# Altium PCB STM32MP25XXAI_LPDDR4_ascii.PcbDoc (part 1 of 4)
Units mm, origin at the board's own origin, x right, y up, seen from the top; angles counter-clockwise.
Board outline 172 x 137 mm, 4 copper layers (Top Layer, Signal Layer 1, Signal Layer 2, Bottom Layer), stack 1.614 mm thick; 188 components, 144 nets, 1216 pads, 838 vias.
Unrouted connection lines stored in the file: 13.
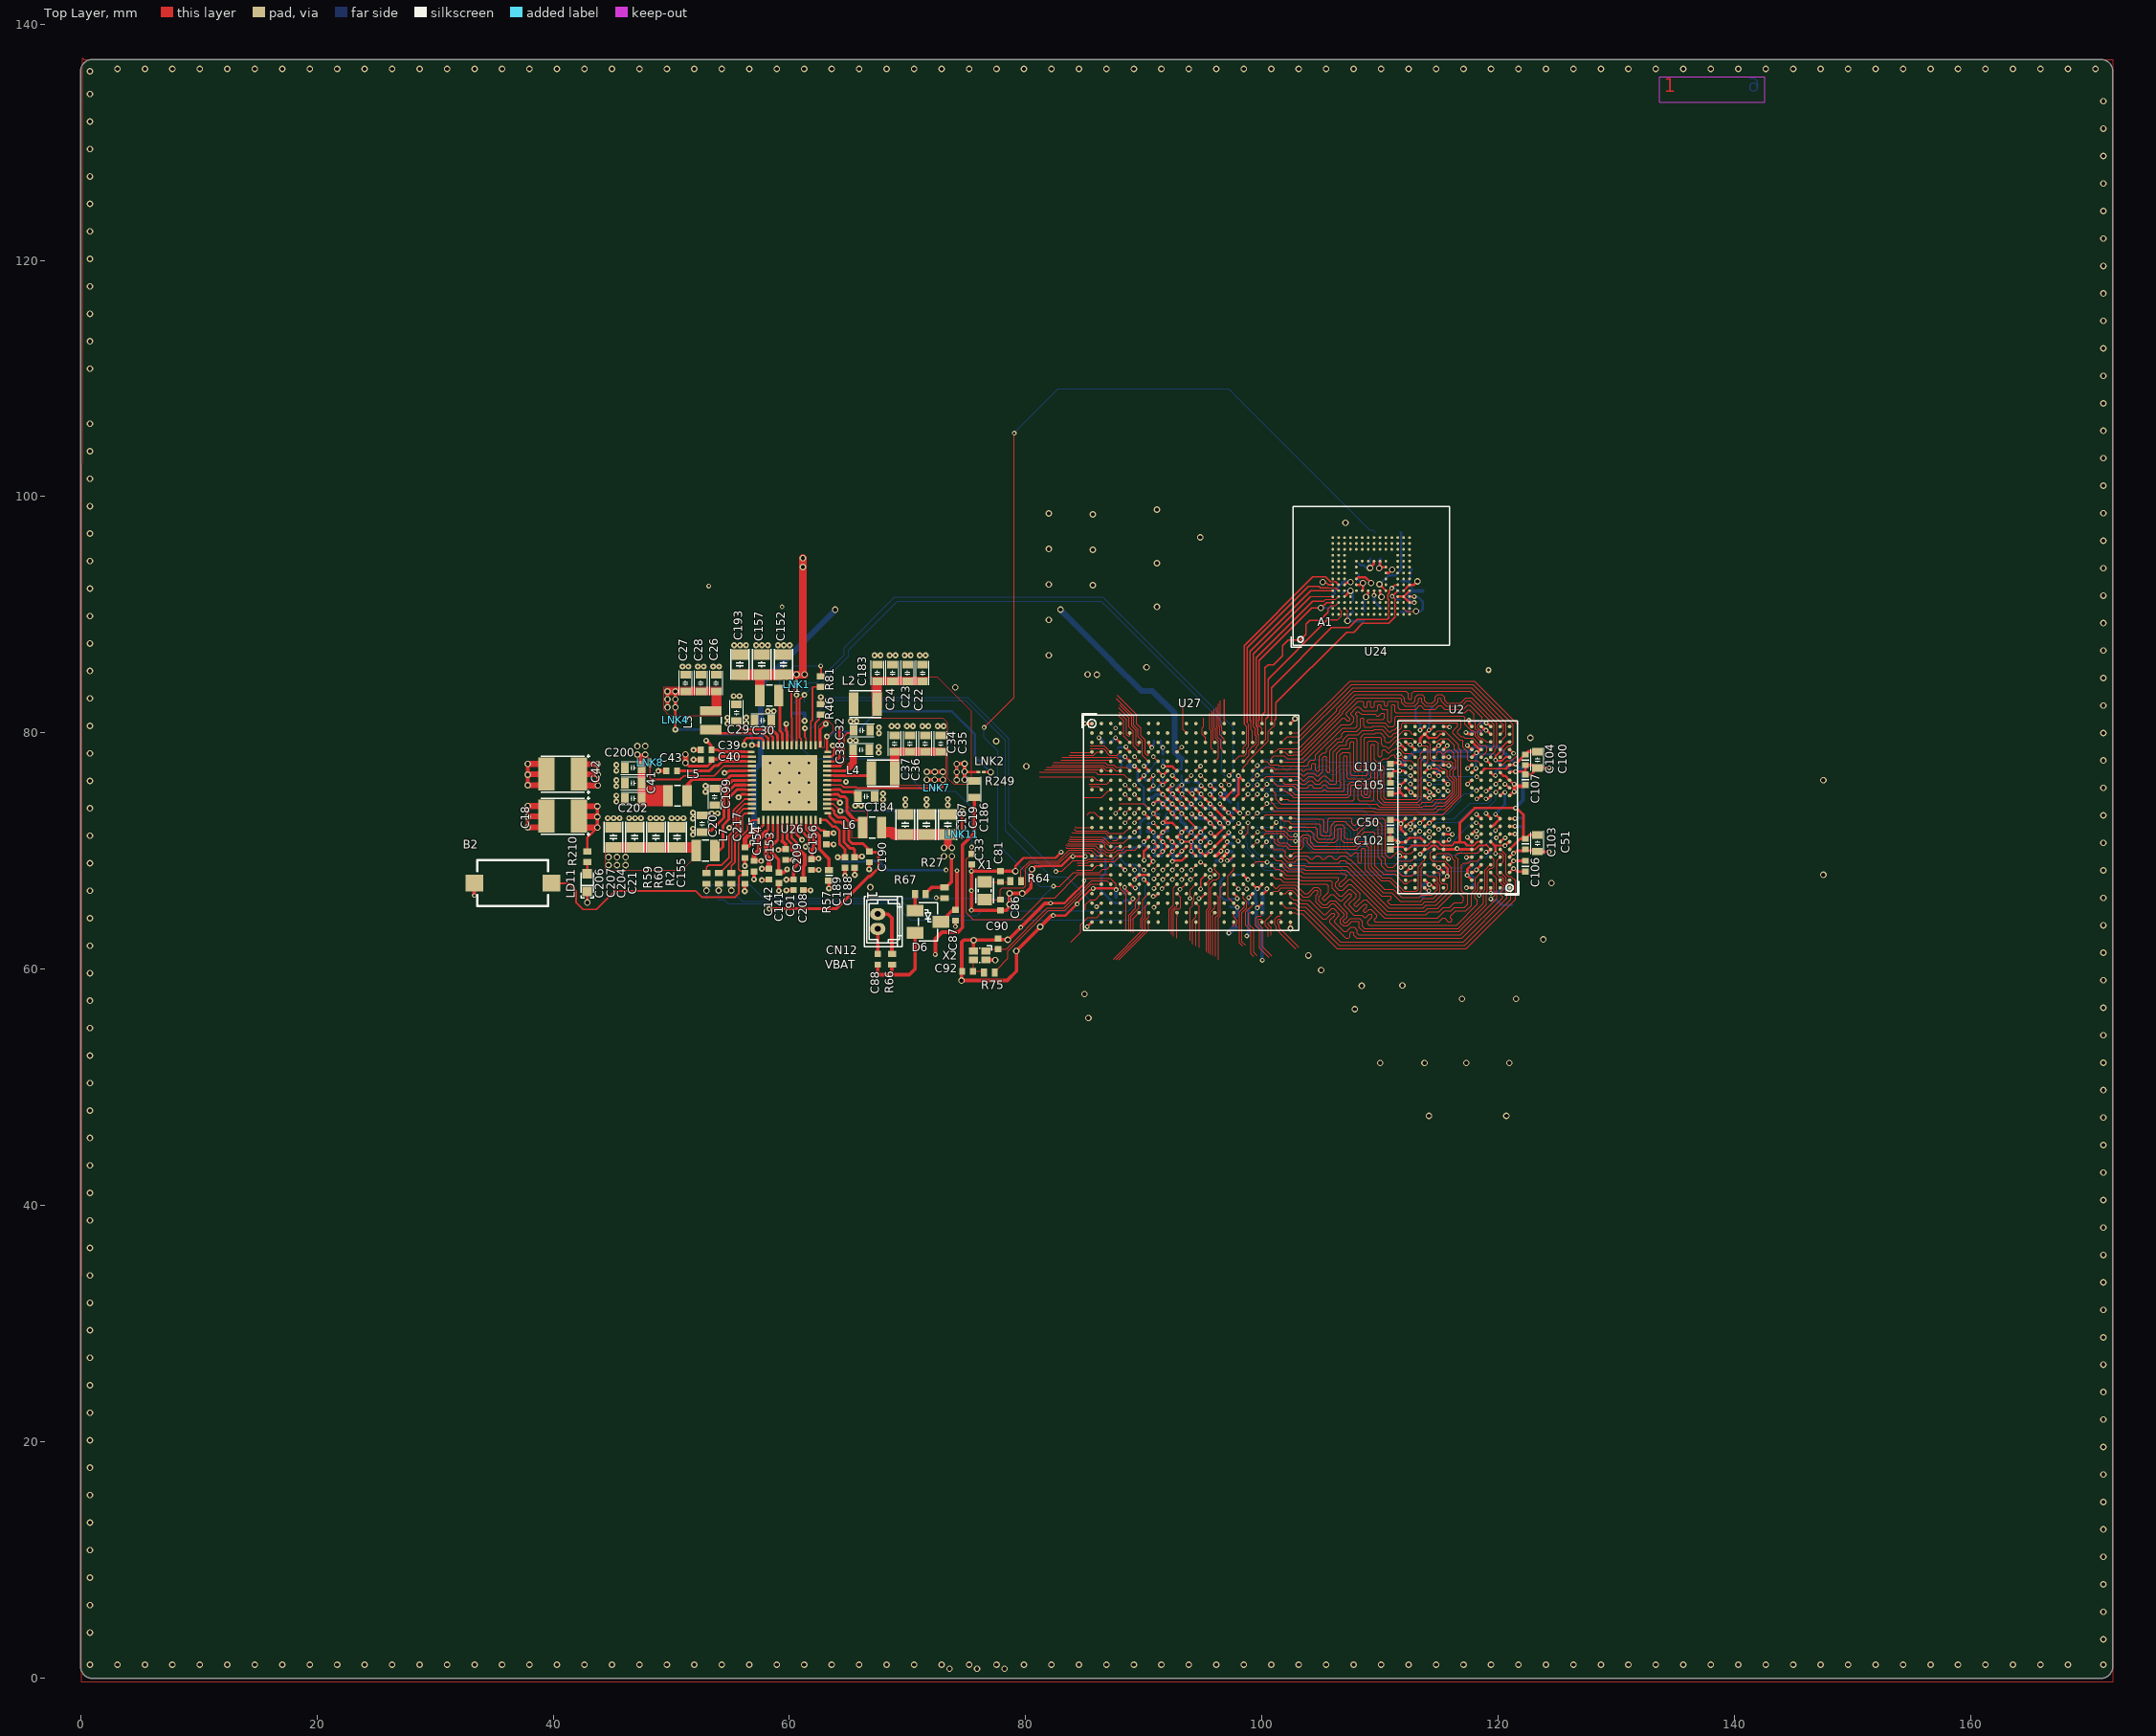
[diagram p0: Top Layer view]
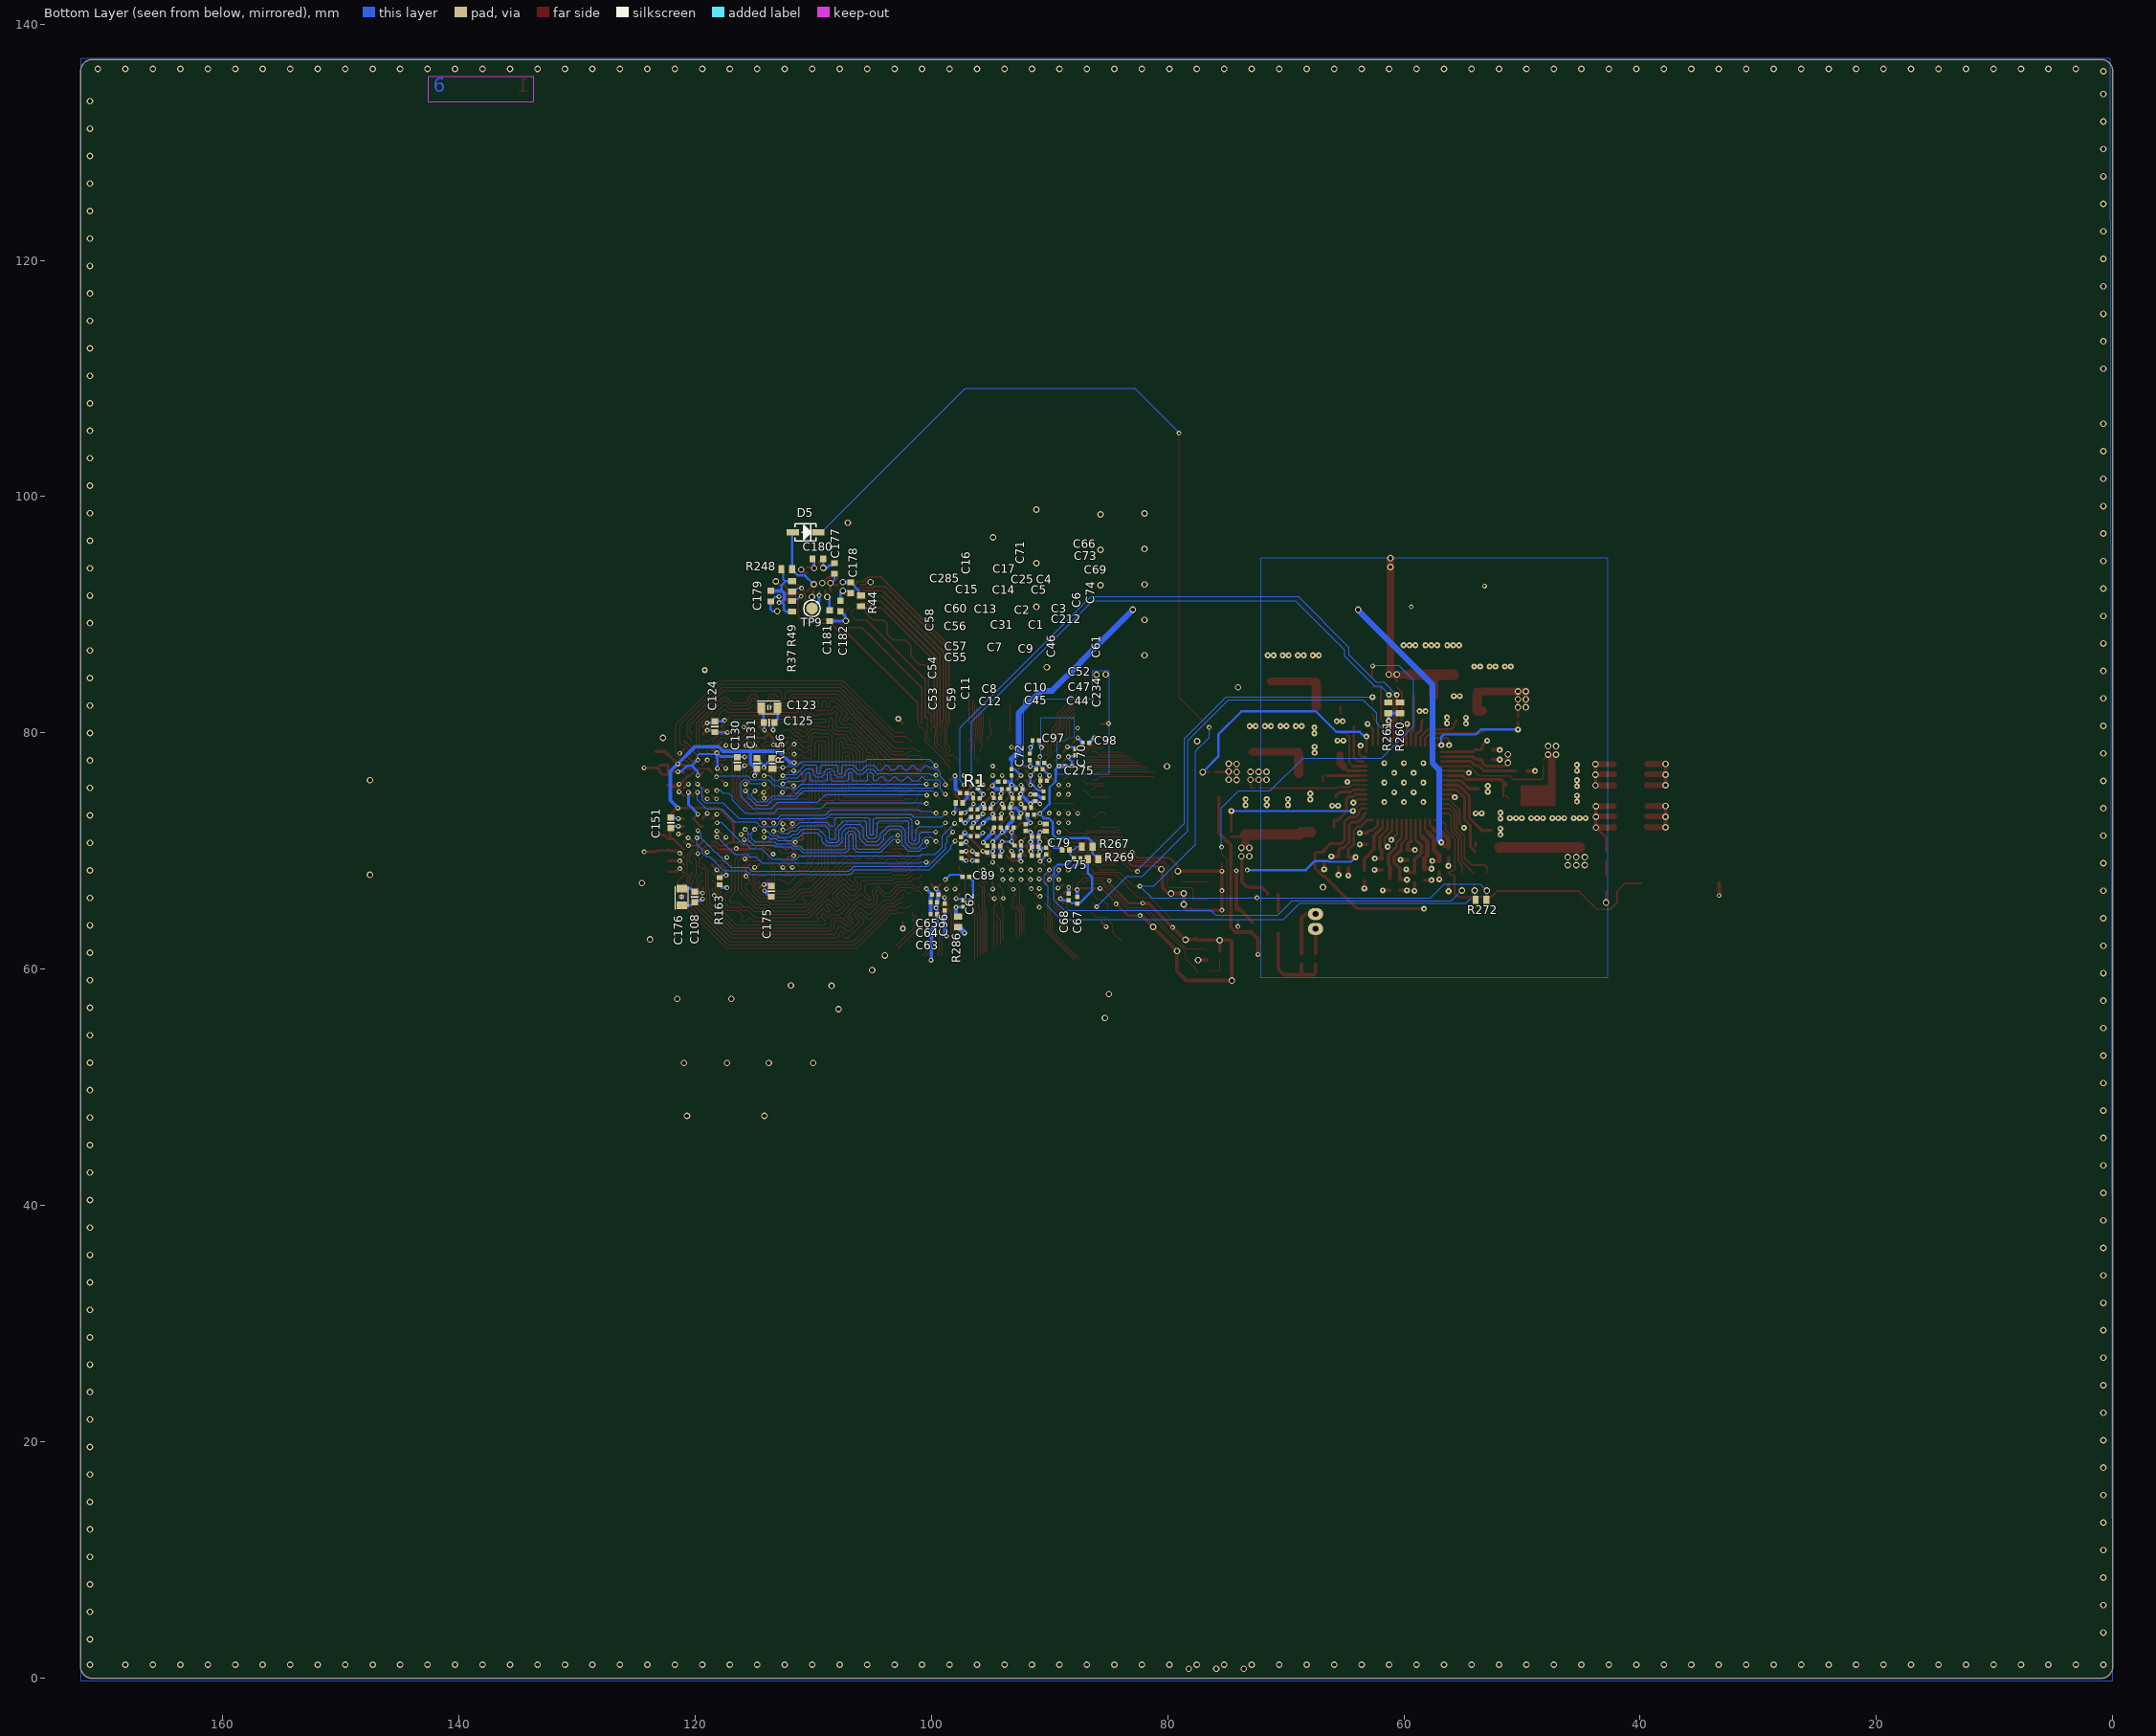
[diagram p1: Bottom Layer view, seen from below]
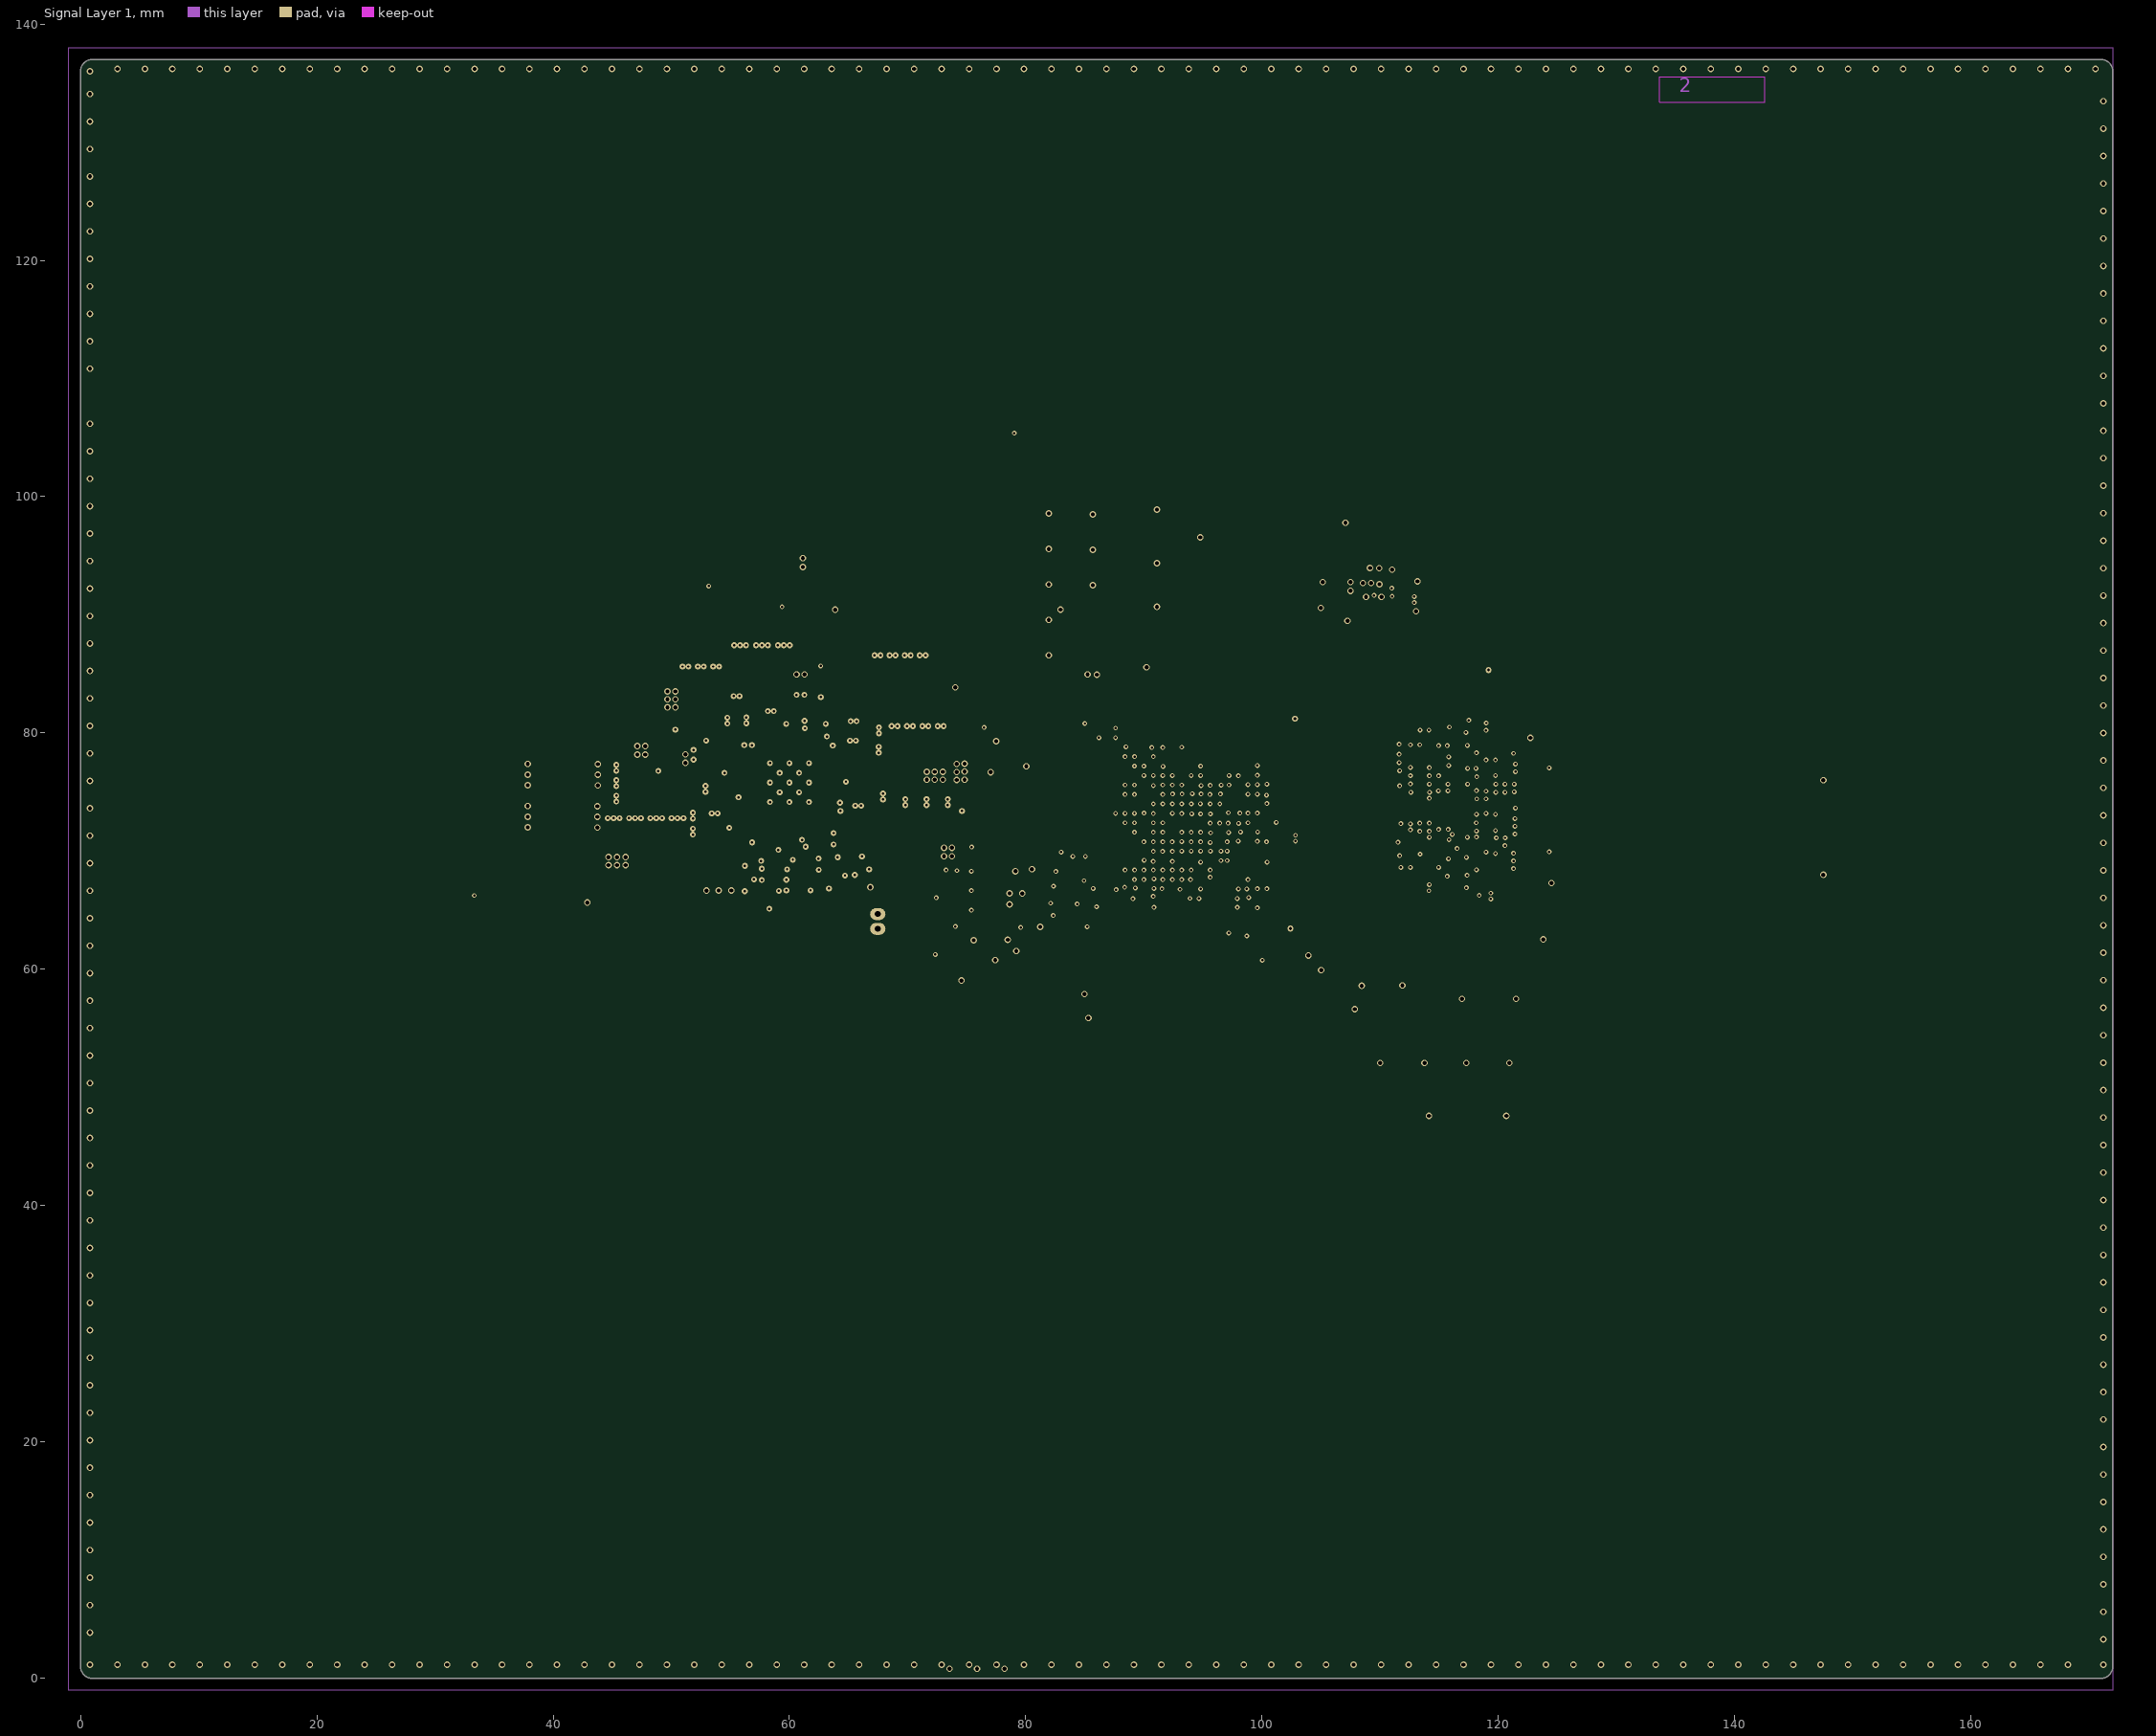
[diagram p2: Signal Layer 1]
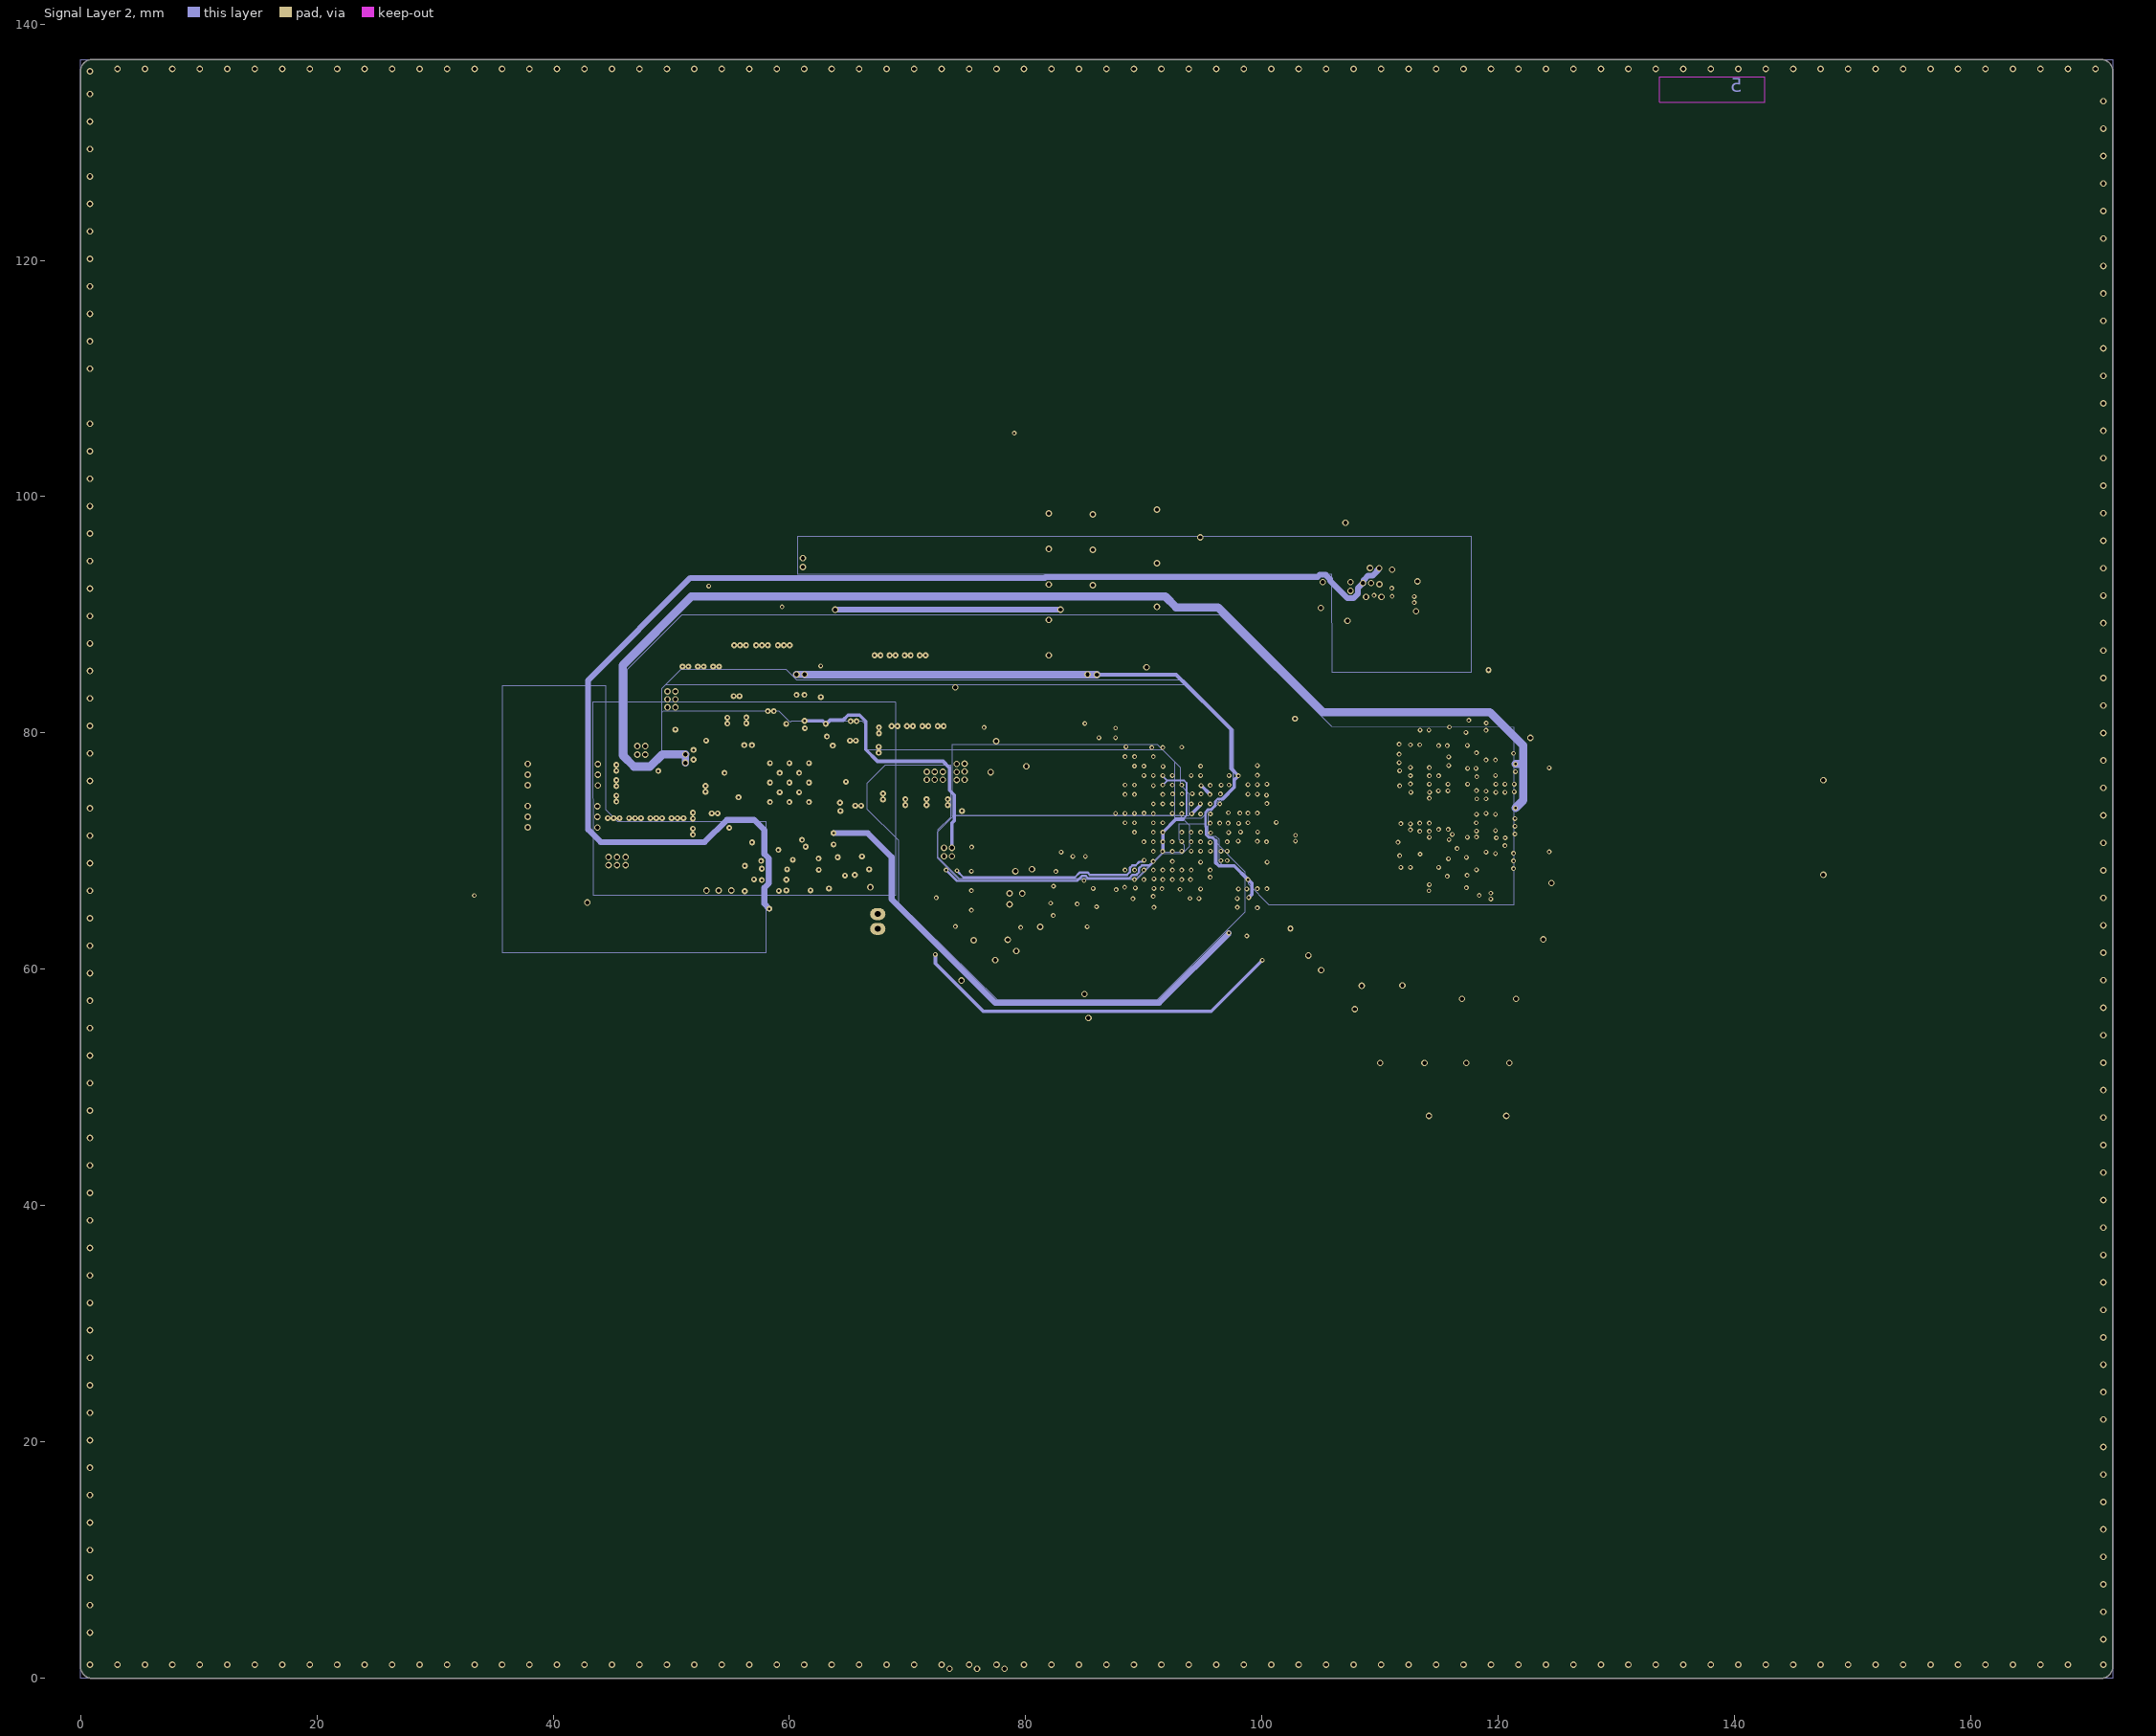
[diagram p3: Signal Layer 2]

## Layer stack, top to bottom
Top Solder: solder mask 0.025, Solder Resist, Dk 3.5
Top Layer: signal copper 0.037
Dielectric 1: prepreg 0.07, Dk 3.8
Signal Layer 1: signal copper 0.035
Dielectric 2: core 1.33, Dk 4.3
Signal Layer 2: signal copper 0.035
Dielectric 3: prepreg 0.07, Dk 3.8
Bottom Layer: signal copper 0.037
Bottom Solder: solder mask 0.025, Solder Resist, Dk 3.5

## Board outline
0,1 0,95 0,136 cw(c1,136) 1,137 171,137 cw(c171,136) 172,136 172,1 cw(c171,1) 171,0 1,0 cw(c1,1)

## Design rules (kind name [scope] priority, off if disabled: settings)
AssemblyTestPointUsage [All] p0: scope1count=1 scope1_0_kind=Board scope1_0_value=Board scope2count=1 scope2_0_kind=Board scope2_0_value=Board commentlength=0
AssemblyTestpoint [All] p0: scope1count=1 scope1_0_kind=Board scope1_0_value=Board scope2count=1 scope2_0_kind=Board scope2_0_value=Board commentlength=0
BoardOutlineClearance Silkscreen [All] p0 off: scope1count=1 scope1_0_kind=Board scope1_0_value=Board scope2count=1 scope2_0_kind=Board scope2_0_value=Board commentlength=90 gap=0 // Protel DXP Scope 1 Expression Was: OnLayer('Top Overlay') or OnLayer('Bottom Overlay')
BoardOutlineClearance [All] p0: scope1count=1 scope1_0_kind=Board scope1_0_value=Board scope2count=1 scope2_0_kind=Board scope2_0_value=Board commentlength=0 gap=0.5
BoardOutlineClearance Silkscreen [OnLayer('Top Overlay') or OnLayer('Bottom Overlay')] p1: gap=0 ignorepadtopadclearanceinfootprint=FALSE
BoardOutlineClearance [All] p2: gap=0.5 ignorepadtopadclearanceinfootprint=FALSE
Clearance Clearance_Default [All] p0: scope1count=1 scope1_0_kind=Board scope1_0_value=Board scope2count=1 scope2_0_kind=Board scope2_0_value=Board commentlength=0 gap=0.1
Clearance Clearance_Default [All] p1: gap=0.1 ignorepadtopadclearanceinfootprint=TRUE except(0: Arc-Hole Track-Hole SMDPad-Hole THPad-Hole Via-Hole Fill-Hole Poly-Hole Region-Hole Text-Hole; 0.09: Track-Track Track-SMDPad)
ComponentClearance [All] p0 off: scope1count=1 scope1_0_kind=Board scope1_0_value=Board scope2count=1 scope2_0_kind=Board scope2_0_value=Board commentlength=0 gap=0.2 collisioncheckmode=3
ComponentClearance [All] p1 off: gap=0.2 collisioncheckmode=3 verticalgap=0 showdistances=FALSE
DiffPairsRouting DiffPairsRouting_DDR_100R [All] p0 off: scope1count=1 scope1_0_kind=Board scope1_0_value=Board scope2count=1 scope2_0_kind=Board scope2_0_value=Board commentlength=78 // Protel DXP Scope 1 Expression Was: InDifferentialPairClass('DPC_DDR_100R')
DiffPairsRouting DiffPairsRouting_DDR_100R [InDifferentialPairClass('DPC_DDR_100R')] p1: maxlimit=0.16 minlimit=0.14 mostfreqgap=0.254 toplayer_mingap=0.16 toplayer_prefgap=0.16 toplayer_minwidth=0.09 toplayer_maxwidth=0.09 toplayer_prefwidth=0.09 bottomlayer_mingap=0.16 bottomlayer_prefgap=0.16 bottomlayer_minwidth=0.09 bottomlayer_maxwidth=0.09 bottomlayer_prefwidth=0.09 impedanceprofiledriven=TRUE impedanceprofileid={5106416E-43F8-41F8-8BCA-F68B3FB1C141} impedanceprofilevalue=100.000000 maxuncoupledlength=12.7
FabricationTestPointUsage [All] p0: scope1count=1 scope1_0_kind=Board scope1_0_value=Board scope2count=1 scope2_0_kind=Board scope2_0_value=Board commentlength=0 valid=0 allowmultiple=FALSE
FabricationTestpoint [All] p0: scope1count=1 scope1_0_kind=Board scope1_0_value=Board scope2count=1 scope2_0_kind=Board scope2_0_value=Board commentlength=0 side=3 testpointundercomponent=TRUE minsize=1.016 maxsize=2.54 preferedsize=1.524 minholesize=0 maxholesize=1.016 preferedholesize=0.813 testpointgrid=0.025
FanoutControl Fanout_Default [All] p0: scope1count=1 scope1_0_kind=Board scope1_0_value=Board scope2count=1 scope2_0_kind=Board scope2_0_value=Board commentlength=30 // Fanout_Default (Default Rule)
FanoutControl Fanout_Small [All] p0 off: scope1count=1 scope1_0_kind=Board scope1_0_value=Board scope2count=1 scope2_0_kind=Board scope2_0_value=Board commentlength=84 // Protel DXP Scope 1 Expression Was: (CompPinCount < 5)   Fanout_Small (Default Rule)
FanoutControl Fanout_SOIC [All] p0 off: scope1count=1 scope1_0_kind=Board scope1_0_value=Board scope2count=1 scope2_0_kind=Board scope2_0_value=Board commentlength=71 // Protel DXP Scope 1 Expression Was: IsSOIC   Fanout_SOIC (Default Rule)
FanoutControl Fanout_LCC [All] p0 off: scope1count=1 scope1_0_kind=Board scope1_0_value=Board scope2count=1 scope2_0_kind=Board scope2_0_value=Board commentlength=69 // Protel DXP Scope 1 Expression Was: IsLCC   Fanout_LCC (Default Rule)
FanoutControl Fanout_BGA [All] p0 off: scope1count=1 scope1_0_kind=Board scope1_0_value=Board scope2count=1 scope2_0_kind=Board scope2_0_value=Board commentlength=69 // Protel DXP Scope 1 Expression Was: IsBGA   Fanout_BGA (Default Rule)
FanoutControl Fanout_BGA [IsBGA] p1: bgadir=Out bgaviamode=Closest fanoutstyle=Auto fanoutdirection=Alternating viagrid=0.025 // Fanout_BGA (Default Rule)
FanoutControl Fanout_LCC [IsLCC] p2: bgadir=Out bgaviamode=Closest fanoutstyle=Auto fanoutdirection=Alternating viagrid=0.025 // Fanout_LCC (Default Rule)
FanoutControl Fanout_SOIC [IsSOIC] p3: bgadir=Out bgaviamode=Closest fanoutstyle=Auto fanoutdirection=Alternating viagrid=0.025 // Fanout_SOIC (Default Rule)
FanoutControl Fanout_Small [(CompPinCount < 5)] p4: bgadir=Out bgaviamode=Closest fanoutstyle=Auto fanoutdirection=OutThenIn viagrid=0.025 // Fanout_Small (Default Rule)
FanoutControl Fanout_Default [All] p5: bgadir=Out bgaviamode=Closest fanoutstyle=Auto fanoutdirection=Alternating viagrid=0.025 // Fanout_Default (Default Rule)
Height [All] p0: scope1count=1 scope1_0_kind=Board scope1_0_value=Board scope2count=1 scope2_0_kind=Board scope2_0_value=Board commentlength=0
HoleSize [All] p0: scope1count=1 scope1_0_kind=Board scope1_0_value=Board scope2count=1 scope2_0_kind=Board scope2_0_value=Board commentlength=0 absolutevalues=TRUE maxlimit=10 minlimit=0.025 maxpercent=80.000 minpercent=20.000
HoleSize [All] p1: absolutevalues=TRUE maxlimit=10 minlimit=0.025 maxpercent=80.000 minpercent=20.000
HoleToHoleClearance [All] p0: scope1count=1 scope1_0_kind=Board scope1_0_value=Board scope2count=1 scope2_0_kind=Board scope2_0_value=Board commentlength=0
HoleToHoleClearance [All] p1: gap=0.25 allowstackedmicrovias=TRUE
LayerPairs [All] p0: scope1count=1 scope1_0_kind=Board scope1_0_value=Board scope2count=1 scope2_0_kind=Board scope2_0_value=Board commentlength=0 enforce=TRUE
Length Length__SINGLE_SDMMC2_50R [All] p0: scope1count=1 scope1_0_kind=NetClass scope1_0_value=NC_SINGLE_SDMMC2_50R scope2count=1 scope2_0_kind=Board scope2_0_value=Board commentlength=0 maxlimit=50 minlimit=0
Length Length__SINGLE_SDMMC2_50R [InNetClass('NC_SINGLE_SDMMC2_50R')] p1: maxlimit=50 minlimit=0
MinimumSolderMaskSliver [All] p0: scope1count=1 scope1_0_kind=Board scope1_0_value=Board scope2count=1 scope2_0_kind=Board scope2_0_value=Board commentlength=0
MinimumSolderMaskSliver [All] p1: minsoldermaskwidth=0.07
NetAntennae [All] p0: scope1count=1 scope1_0_kind=Board scope1_0_value=Board scope2count=1 scope2_0_kind=Board scope2_0_value=Board commentlength=0
PasteMaskExpansion [All] p0: scope1count=1 scope1_0_kind=Board scope1_0_value=Board scope2count=1 scope2_0_kind=Board scope2_0_value=Board commentlength=0 expansion=0
PlaneClearance [All] p0: scope1count=1 scope1_0_kind=Board scope1_0_value=Board scope2count=1 scope2_0_kind=Board scope2_0_value=Board commentlength=0 clearance=0.508
PlaneConnect [All] p0: scope1count=1 scope1_0_kind=Board scope1_0_value=Board scope2count=1 scope2_0_kind=Board scope2_0_value=Board commentlength=0 planeconnectstyle=Direct reliefexpansion=0.508 reliefentries=4 reliefconductorwidth=0.21 reliefairgap=0.21
PlaneConnect [All] p1: planeconnectstyle=Direct reliefexpansion=0.508 reliefentries=4 reliefconductorwidth=0.21 reliefairgap=0.21
PolygonConnect PolygonConnect_Default [All] p0: scope1count=1 scope1_0_kind=Board scope1_0_value=Board scope2count=1 scope2_0_kind=Board scope2_0_value=Board commentlength=0 connectstyle=Direct reliefconductorwidth=0.25 reliefentries=4 polygonreliefangle="90 Angle"
PolygonConnect PolygonConnect_Default [All] p1: connectstyle=Direct reliefconductorwidth=0.25 reliefentries=4 polygonreliefangle="90 Angle" airgapwidth=0.25
RoutingCorners [All] p0: scope1count=1 scope1_0_kind=Board scope1_0_value=Board scope2count=1 scope2_0_kind=Board scope2_0_value=Board commentlength=0 cornerstyle=45-Degree minsetback=2.54 maxsetback=2.54
RoutingLayers [All] p0: scope1count=1 scope1_0_kind=Board scope1_0_value=Board scope2count=1 scope2_0_kind=Board scope2_0_value=Board commentlength=0 top layer=Automatic mid layer 1=Automatic mid layer 4=Automatic bottom layer=Automatic
RoutingPriority [All] p0: scope1count=1 scope1_0_kind=Board scope1_0_value=Board scope2count=1 scope2_0_kind=Board scope2_0_value=Board commentlength=0
RoutingTopology [All] p0: scope1count=1 scope1_0_kind=Board scope1_0_value=Board scope2count=1 scope2_0_kind=Board scope2_0_value=Board commentlength=0 topology=Shortest
RoutingVias RoutingVias_Default [All] p0: scope1count=1 scope1_0_kind=Board scope1_0_value=Board scope2count=1 scope2_0_kind=Board scope2_0_value=Board commentlength=0 holewidth=0.15 width=0.4 viastyle="Through Hole" minholewidth=0.15 minwidth=0.4 maxholewidth=0.35 maxwidth=0.6
RoutingVias RoutingVias_Default [All] p1: holewidth=0.15 width=0.4 viastyle="Through Hole" minholewidth=0.15 minwidth=0.4 maxholewidth=0.35 maxwidth=0.6 viatemplateguid#1={BF886351-5902-4D8E-87A9-DD407FAE4AFA} viatemplateguid#2={A479BBDC-94B7-4D18-B59D-B7A18B767B5F} viatemplateguid#3={564DD7E2-F718-4BCE-8A99-5417C9FECCB6} viatemplateguid#4={BB8F4C89-420F-4EBC-9772-FD82009DE81A} viatemplateguid#5={3FF096CA-B7A5-4E0B-A50A-8B2CD18CCC19} viatemplatename#1=v50h25m30mx30 viatemplatename#2=v55h35m40mx40 viatemplatename#3=v40h20m0mx0 viatemplatename#4=v40h20m25mx25 viatemplatename#5=v50h25m0mx0
ShortCircuit ShortCircuit_Link200 [All] p0: scope1count=1 scope1_0_kind=PadClass scope1_0_value=PC_LINK200 scope2count=1 scope2_0_kind=Board scope2_0_value=Board commentlength=0 allowed=TRUE
ShortCircuit ShortCircuit_Link200 [InPadClass('PC_LINK200')] p1: allowed=TRUE
SilkToBoardRegionClearance [All] p0: scope1count=1 scope1_0_kind=Board scope1_0_value=Board scope2count=1 scope2_0_kind=Board scope2_0_value=Board commentlength=0
SilkToSilkClearance [All] p0: scope1count=1 scope1_0_kind=Board scope1_0_value=Board scope2count=1 scope2_0_kind=Board scope2_0_value=Board commentlength=0
SilkToSilkClearance [All] p1: silktosilkclearance=0.2
SilkToSolderMaskClearance [All] p0 off: scope1count=1 scope1_0_kind=Board scope1_0_value=Board scope2count=1 scope2_0_kind=Board scope2_0_value=Board commentlength=44 // Protel DXP Scope 1 Expression Was: IsPad
SilkToSolderMaskClearance [IsPad] p1: minsilkscreentomaskgap=0.015 clearancetoexposedcopper=TRUE
SolderMaskExpansion [All] p0: scope1count=1 scope1_0_kind=Board scope1_0_value=Board scope2count=1 scope2_0_kind=Board scope2_0_value=Board commentlength=0 expansion=0.1
SolderMaskExpansion [All] p1: expansion=0.1 istentingtop=FALSE
UnRoutedNet [All] p0: scope1count=1 scope1_0_kind=Board scope1_0_value=Board scope2count=1 scope2_0_kind=Board scope2_0_value=Board commentlength=0
UnpouredPolygon [All] p0: scope1count=1 scope1_0_kind=Board scope1_0_value=Board scope2count=1 scope2_0_kind=Board scope2_0_value=Board commentlength=0
ViasUnderSMD [All] p0: scope1count=1 scope1_0_kind=PadClass scope1_0_value=PC_VIAS-IN-PAD_OK scope2count=1 scope2_0_kind=Board scope2_0_value=Board commentlength=0 allowed=TRUE
ViasUnderSMD [InPadClass('PC_VIAS-IN-PAD_OK')] p1: allowed=TRUE
Width Width_Default [All] p0: scope1count=1 scope1_0_kind=NetClass scope1_0_value="All Nets" scope2count=1 scope2_0_kind=Board scope2_0_value=Board commentlength=0 maxlimit=10 minlimit=0.09 preferedwidth=0.1
Width Width_Default [InNetClass('All Nets')] p1: maxlimit=10 minlimit=0.09 preferedwidth=0.1
16 further rules are at their usual default settings.

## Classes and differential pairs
net class eMMC.SDMMC2_D[0..7]: eMMC.SDMMC2_D0 eMMC.SDMMC2_D1 eMMC.SDMMC2_D2 eMMC.SDMMC2_D3 eMMC.SDMMC2_D4 eMMC.SDMMC2_D5 eMMC.SDMMC2_D6 eMMC.SDMMC2_D7
component class "U_STM32MP25XXAI Power": C1 C2 C3 C4 C5 C6 C7 C8 C9 C10 C11 C12 C13 C14 C15 C16 C17 C25 C31 C44 C45 C46 C47 C52 C53 C54 C55 C56 C57 C58 C59 C60 C61 C62 C63 C64 C65 C66 C67 C68 C69 C70 C71 C72 C73 C74 C75 C79 C87 C88 C89 C96 C97 C98 C212 C234 C275 C285 CN12 D6 R66 R67 R249 R267 R269 R286
component class "U_STM32MP25XXAI I_Os": C33 C81 C86 C90 C92 R27 R64 R75 R260 R261 R272 U27 X1 X2
component class U_PMIC: B2 C18 C19 C20 C21 C22 C23 C24 C26 C27 C28 C29 C30 C32 C34 C35 C36 C37 C38 C39 C40 C41 C42 C43 C91 C141 C142 C152 C153 C154 C155 C156 C157 C183 C184 C186 C187 C188 C189 C190 C193 C199 C200 C202 C204 C206 C207 C208 C209 C217 L1 L2 L3 L4 L5 L6 L7 LD11 LNK1 LNK2 LNK4 LNK7 LNK8 LNK11 R2 R46 R57 R59 R60 R81 R210 U26
component class U_eMMC: C177 C178 C179 C180 C181 C182 D5 R37 R44 R49 R248 TP9 U24
component class U_2_LPDDR4_32bits: C50 C51 C100 C101 C102 C103 C104 C105 C106 C107 C108 C123 C124 C125 C130 C131 C151 C175 C176 R1 R156 R163 U2
differential pair DDR_DQS1_B: +DDR_DQS1_B_P -DDR_DQS1_B_N
differential pair DDR_DQS1_A: +DDR_DQS1_A_P -DDR_DQS1_A_N
differential pair DDR_DQS0_B: +DDR_DQS0_B_P -DDR_DQS0_B_N
differential pair DDR_DQS0_A: +DDR_DQS0_A_P -DDR_DQS0_A_N
differential pair DDR_CLK_B: +DDR_CLK_B_P -DDR_CLK_B_N
differential pair " ": +DDR_CLK_A_P -DDR_CLK_A_N

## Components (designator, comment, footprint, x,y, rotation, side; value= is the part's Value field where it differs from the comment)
B2 "SW_PUSH_SMD_2P" SWI_WE_434121025816 36.59,67.295 r0 top
C1 "Capacitor" C0201_MURATA_GRM033_H0P3 92.825,72.825 r0 bottom
C2 "Capacitor" C0201_MURATA_GRM033_H0P3 93.601,73.65 r180 bottom
C3 "Capacitor" C0201_MURATA_GRM033_H0P3 91.825,73.65 r180 bottom
C4 "Capacitor" C0201_MURATA_GRM033_H0P3 92.55,75.25 r0 bottom
C5 "Capacitor" C0201_MURATA_GRM033_H0P3 92.826,74.475 r180 bottom
C6 "Capacitor" C0201_MURATA_GRM033_H0P3 91.2,74.525 r270 bottom
C7 "Capacitor" C0201_MURATA_GRM033_H0P3 94.4,72 r0 bottom
C8 "Capacitor" C0201_MURATA_GRM033_H0P3 94.425,70.425 r180 bottom
C9 "Capacitor" C0201_MURATA_GRM033_H0P3 93.3,72 r180 bottom
C10 "Capacitor" C0201_MURATA_GRM033_H0P3 92.675,70.48 r0 bottom
C11 "Capacitor" C0201_MURATA_GRM033_H0P3 95.25,70.175 r270 bottom
C12 "Capacitor" C0201_MURATA_GRM033_H0P3 94.425,69.575 r180 bottom
C13 "Capacitor" C0201_MURATA_GRM033_H0P3 95.232,73.625 r0 bottom
C14 "Capacitor" C0201_MURATA_GRM033_H0P3 94.425,74.48 r180 bottom
C15 "Capacitor" C0201_MURATA_GRM033_H0P3 96.175,74.475 r180 bottom
C16 "Capacitor" C0201_MURATA_GRM033_H0P3 96.075,75.6 r90 bottom
C17 "Capacitor" C0201_MURATA_GRM033_H0P3 94.05,75.875 r0 bottom
C18 "Cap_POL_TANA" CPOL_TCJ-B_1210_H210 40.812,72.961 r180 top
C19 "Capacitor" C0805 71.6,72.25 r270 top
C20 "Capacitor" C0603 52.6,72.325 r270 top
C21 "Capacitor" C0805 50.5,71.173 r270 top
C22 "Capacitor" C0603 71.275,85.075 r270 top
C23 "Capacitor" C0603 70,85.075 r270 top
C24 "Capacitor" C0603 68.725,85.075 r270 top
C25 "Capacitor" C0201_MURATA_GRM033_H0P3 93.75,75.25 r0 bottom
C26 "Capacitor" C0603 53.8,84.225 r270 top
C27 "Capacitor" C0603 51.2,84.225 r270 top
C28 "Capacitor" C0603 52.5,84.225 r270 top
C29 "Capacitor" C0603 55.525,81.725 r270 top
C30 "Capacitor" C0603 57.75,81.075 r0 top
C31 "Capacitor" C0201_MURATA_GRM033_H0P3 94.4,72.775 r180 bottom
C32 "Capacitor" C0603 66.125,80.225 r180 top
C33 "Capacitor" C0402 75.425,69.325 r90 top
C34 "Capacitor" C0603 71.5,79.1 r270 top
C35 "Capacitor" C0603 72.8,79.1 r270 top
C36 "Capacitor" C0603 70.2,79.1 r270 top
C37 "Capacitor" C0603 68.9,79.1 r270 top
C38 "Capacitor" C0603 66.075,78.575 r180 top
C39 "Capacitor" C0402 52.945,78.575 r0 top
C40 "Capacitor" C0402 52.945,77.75 r0 top
C41 "Capacitor" C0603 46.775,75.75 r0 top
C42 "Cap_POL_TANA" CPOL_TCJ-B_1210_H210 40.812,76.523 r180 top
C43 "Capacitor" C0402 50.035,76.8 r0 top
C44 "Capacitor" C0201_MURATA_GRM033_H0P3 91.2,69.6 r180 bottom
C45 "Capacitor" C0201_MURATA_GRM033_H0P3 92.8,69.6 r0 bottom
C46 "Capacitor" C0201_MURATA_GRM033_H0P3 92.025,72 r270 bottom
C47 "Capacitor" C0201_MURATA_GRM033_H0P3 91.2,70.388 r180 bottom
C50 "Capacitor" C0402 110.85,72.2 r270 top
C51 "Capacitor" C0603 123.3,70.675 r90 top
C52 "Capacitor" C0201_MURATA_GRM033_H0P3 91.2,71.2 r0 bottom
C53 "Capacitor" C0201_MURATA_GRM033_H0P3 97.45,69.675 r270 bottom
C54 "Capacitor" C0201_MURATA_GRM033_H0P3 97.475,70.9 r90 bottom
C55 "Capacitor" C0201_MURATA_GRM033_H0P3 96.375,71.275 r180 bottom
C56 "Capacitor" C0201_MURATA_GRM033_H0P3 96.349,72.875 r180 bottom
C57 "Capacitor" C0201_MURATA_GRM033_H0P3 96.301,71.974 r0 bottom
C58 "Capacitor" C0201_MURATA_GRM033_H0P3 97.5,72.925 r90 bottom
C59 "Capacitor" C0201_MURATA_GRM033_H0P3 96.1,69.45 r90 bottom
C60 "Capacitor" C0201_MURATA_GRM033_H0P3 96.356,73.524 r0 bottom
C61 "Capacitor" C0201_H0P5 90.317,71.988 r90 bottom
C62 "Capacitor" C0201_MURATA_GRM033_H0P3 97.3,65.575 r270 bottom
C63 "Capacitor" C0201_MURATA_GRM033_H0P3 99.775,64.675 r180 bottom
C64 "Capacitor" C0201_MURATA_GRM033_H0P3 99.775,65.675 r180 bottom
C65 "Capacitor" C0201_MURATA_GRM033_H0P3 99.65,66.325 r180 bottom
C66 "Capacitor" C0201_MURATA_GRM033_H0P3 90.7,77.475 r180 bottom
C67 "Capacitor" C0201_MURATA_GRM033_H0P3 87.63,65.845 r270 bottom
C68 "Capacitor" C0201_MURATA_GRM033_H0P3 88.375,66.125 r270 bottom
C69 "Capacitor" C0201_MURATA_GRM033_H0P3 90.48,75.97 r0 bottom
C70 "Capacitor" C0201_MURATA_GRM033_H0P3 87.8,78.375 r90 bottom
C71 "Capacitor" C0201_MURATA_GRM033_H0P3 93.201,76.675 r90 bottom
C72 "Capacitor" C0201_MURATA_GRM033_H0P3 91.675,77.975 r270 bottom
C73 "Capacitor" C0201_MURATA_GRM033_H0P3 90.85,76.925 r0 bottom
C74 "Capacitor" C0201_MURATA_GRM033_H0P3 90.5,74.775 r90 bottom
C75 "Capacitor" C0201_MURATA_GRM033_H0P3 87.65,69.425 r0 bottom
C79 "Capacitor" C0201_H0P5 88.6,70.125 r180 bottom
C81 "Capacitor" C0402 77.85,67.85 r90 top
C86 "Capacitor" C0402 77.85,65.45 r270 top
C87 "" C0402 74.05,64.575 r90 top
C88 "Capacitor" C0402 67.475,60.85 r270 top
C89 "Capacitor" C0201_MURATA_GRM033_H0P3 97.075,67.825 r0 bottom
C90 "Capacitor" C0402 77.65,62.15 r270 top
C91 "Capacitor" C0402 60.345,67.16 r270 top
C92 "Capacitor" C0402 75.075,59.825 r180 top
C96 "Capacitor" C0201_MURATA_GRM033_H0P3 98.85,65.275 r90 bottom
C97 "Capacitor" C0201_MURATA_GRM033_H0P3 91.15,79.375 r180 bottom
C98 "Capacitor" C0201_MURATA_GRM033_H0P3 86.9,79.175 r0 bottom
C100 "Capacitor" C0603 123.3,77.725 r90 top
C101 "Capacitor" C0402 110.85,76.925 r90 top
C102 "Capacitor" C0402 110.85,70.575 r270 top
C103 "Capacitor" C0402 122.275,70.6 r90 top
C104 "Capacitor" C0402 122.275,77.725 r90 top
C105 "Capacitor" C0402 110.85,75.325 r270 top
C106 "Capacitor" C0402 122.275,68.725 r270 top
C107 "Capacitor" C0402 122.275,76.05 r90 top
C108 "Capacitor" C0402 120.025,66.125 r90 bottom
C123 "Capacitor" C0603 113.7,82.15 r0 bottom
C124 "Capacitor" C0402 118.3,80.525 r90 bottom
C125 "Capacitor" C0402 113.725,80.9 r180 bottom
C130 "Capacitor" C0402 116.4,77.5 r90 bottom
C131 "Capacitor" C0402 114.75,77.425 r270 bottom
C141 "Capacitor" C0402 59.1,67.75 r270 top
C142 "Capacitor" C0402 58.275,68.06 r270 top
C151 "Capacitor" C0402 122.05,72.4 r270 bottom
C152 "Capacitor" C0805 59.5,85.8 r270 top
C153 "Capacitor" C0402 59.675,69.72 r90 top
C154 "Capacitor" C0402 57,68.725 r90 top
C155 "Capacitor" C0402 56.227,67.695 r90 top
C156 "Capacitor" C0402 63.125,71.02 r90 top
C157 "Capacitor" C0805 57.65,85.8 r270 top
C175 "Capacitor" C0402 113.55,66.6 r270 bottom
C176 "Capacitor" C0603 121.125,66.125 r270 bottom
C177 "Capacitor" C0402 108.2,93.925 r270 bottom
C178 "Capacitor" C0402 106.825,92.3 r90 bottom
C179 "Capacitor" C0402 113.59,91.58 r90 bottom
C180 "Capacitor" C0402 109.6,94.739 r0 bottom
C181 "Capacitor" C0402 108.6,89.925 r270 bottom
C182 "Capacitor" C0402 107.685,90.75 r270 bottom
C183 "Capacitor" C0603 67.45,85.075 r270 top
C184 "Capacitor" C0603 66.497,74.625 r180 top
C186 "Capacitor" C0805 73.4,72.25 r270 top
C187 "Capacitor" C0805 69.8,72.25 r270 top
C188 "Capacitor" C0402 65.525,69.04 r90 top
C189 "Capacitor" C0402 64.7,69.04 r90 top
C190 "Capacitor" C0402 66.75,69.515 r270 top
C193 "Capacitor" C0805 55.8,85.8 r270 top
C199 "Capacitor" C0603 53.675,74.6 r90 top
C200 "Capacitor" C0603 46.775,77.05 r0 top
C202 "Capacitor" C0603 46.775,74.45 r0 top
C204 "Capacitor" C0805 48.7,71.173 r270 top
C206 "Capacitor" C0805 45.1,71.173 r270 top
C207 "Capacitor" C0805 46.9,71.173 r270 top
C208 "Capacitor" C0402 61.17,67.16 r270 top
C209 "Capacitor" C0402 61.85,68.87 r90 top
C212 "Capacitor" C0201_MURATA_GRM033_H0P3 91.585,73.1 r180 bottom
C217 "Capacitor" C0402 56.225,69.87 r270 top
C234 "Capacitor" C0201_MURATA_GRM033_H0P3 90.275,70.01 r270 bottom
C275 "Capacitor" C0201_MURATA_GRM033_H0P3 88.35,77.2 r0 bottom
C285 "Capacitor" C0201_MURATA_GRM033_H0P3 97.28,74.91 r0 bottom
CN12 "" CON_MOLEX_53047-0210 67.475,64.05 r270 top
D5 "BAT60JFILM" DIO_SOD323 110.65,96.975 r180 bottom
D6 "DIODE_3P_DUAL_COMMON_CATHODE" DIO_SOT23 71.725,64.025 r270 top
L1 "Inductor" IND_2016_MURATA_LQM2MPN2R2NG0 58.295,83.175 r180 top
L2 "Inductor" IND_2520_TOKO_DFE252012P 66.415,82.45 r0 top
L3 "Inductor" IND_2016_MURATA_LQM2MPN2R2NG0 53.35,81.075 r90 top
L4 "Inductor" IND_2520_TOKO_DFE252012P 67.925,76.6 r0 top
L5 "Inductor" IND_2016_MURATA_LQM2MPN2R2NG0 50.525,74.7 r180 top
L6 "Inductor" IND_2016_MURATA_LQM2MPN2R2NG0 67,72 r0 top
L7 "Inductor" IND_2016_MURATA_LQM2MPN2R2NG0 52.9,70.05 r180 top
LD11 "LED_green" LED_0603_OSRAM_LG-Q396-PS-35_GREEN_1A2K_H0P4 42.887,67.327 r270 top
LNK1 "link_200" LINK200 60.6,84.123 r0 top
LNK2 "link_200" LINK200 76.219,76.687 r90 top
LNK4 "link_200" LINK200 50.35,81.125 r180 top
LNK7 "link_200" LINK200 72.45,75.35 r270 top
LNK8 "link_200" LINK200 48.2,77.498 r0 top
LNK11 "link_200" LINK200 74.6,71.44 r180 top
R1 "Resistor" R0201_H0P23 97.627,74.077 r0 bottom
R2 "" R0402 55.08,67.695 r90 top
R27 "Resistor" R0402 73.125,66.475 r90 top
R37 "Resistor" R0402 111.775,90.725 r270 bottom
R44 "Resistor" R0402 105.95,91.18 r90 bottom
R46 "" R0402 62.65,81.998 r270 top
R49 "Resistor" R0402 111.775,92.4 r90 bottom
R57 "" R0402 63.35,67.95 r90 top
R59 "" R0402 52.98,67.695 r90 top
R60 "" R0402 54.03,67.695 r90 top
R64 "" R0402 79.15,67.45 r180 top
R66 "Resistor" R0402 68.675,60.845 r270 top
R67 "Resistor" R0402 71.075,66.375 r0 top
R75 "" R0402 76.925,59.725 r0 top
R81 "" R0402 62.663,84.348 r270 top
R156 "Resistor" R0402 113.425,77.425 r270 bottom
R163 "Resistor" R0201_H0P23 117.9,67.45 r90 bottom
R210 "Resistor" R0402 42.887,69.52 r270 top
R248 "Resistor" R0402 112.232,93.855 r0 bottom
R249 "Resistor" R0603 75.65,75.25 r270 top
R260 "Resistor" R0402 60.33,82.13 r270 bottom
R261 "Resistor" R0402 61.305,82.13 r270 bottom
R267 "" R0402 86.8,70.375 r180 bottom
R269 "" R0402 86.304,69.315 r0 bottom
R272 "Resistor" R0402 53.475,65.879 r0 bottom
R286 "" R0402 97.725,64.025 r90 bottom
TP9 "Test Point" TP_SMD_1MM 110.091,90.54 r90 bottom
U2 "MT53E1G32D2FW-046 WT:C" ICC_TFBGA200_10X14P5_P080_H1P05_PS0P3 116.55,73.725 r180 top
U24 "eMMC_THGBMTG5D1LBAIL" ICC_P-WFBGA153_13X11P5_P050 109.23,93.292 r0 top
U26 "STPMIC25APQR" ICC_QFN56-EPAD_6P5X6P5_P040 60,75.8 r90 top
U27 "STM32MP257FAI3" ICC_LFBGA436_18X18_P080_H1P70_STM32MP257_CODE-B0D1 94,72.4 r0 top locked
X1 "XTAL_2_PINS" CRY_NX2012SA_2P 76.525,66.65 r270 top
X2 "XTAL_4_PINS" CRY_NX1612SA_4P 76.098,61.176 r180 top

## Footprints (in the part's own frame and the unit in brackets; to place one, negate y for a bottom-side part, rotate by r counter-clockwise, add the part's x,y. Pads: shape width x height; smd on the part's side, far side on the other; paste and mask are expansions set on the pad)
C0201_H0P5 [mm] "MCD-01534"
  rect 0.4x0.5 smd mask+0: 1(-0.3,0) 2(0.3,0)
C0201_MURATA_GRM033_H0P3 [mm] "GRM033R60J105ME11"
  rect 0.35x0.35 smd mask+0: 1(-0.275,0) 2(0.275,0)
C0402 [mm]
  rect 0.51x0.56 smd mask+0: 1(-0.45,0) 2(0.45,0)
C0603 [mm]
  rect 0.64x0.89 smd mask+0: 1(-0.7,0) 2(0.7,0)
  silkscreen extent -1.05,-0.55 1.02,0.55
C0805 [mm]
  rect 0.9x1.4 smd mask+0: 1(-0.85,0) 2(0.85,0)
  silkscreen extent -1.3,-0.77 1.3,0.77
CON_MOLEX_53047-0210 [mm]
  oval 1x1.3 hole 0.5 mask+0: 1(-0.625,0) 2(0.625,0)
  silkscreen extent -2.12,-1.15 2.13,2.05
CPOL_TCJ-B_1210_H210 [mm] "MCD-01791"
  rect 1.35x2.8 smd mask+0: 1(-1.375,0) 2(1.375,0)
  silkscreen extent -2.33,-1.68 1.85,1.68
CRY_NX1612SA_4P [mm] "MCD-02262"
  rect 0.75x0.6 smd mask+0: 1(-0.525,-0.375) 2(0.525,-0.375) 3(0.525,0.375) 4(-0.525,0.375)
  silkscreen extent -1.02,-0.8 0.03,0.6
CRY_NX2012SA_2P [mm]
  rect 1x1.25 smd mask+0: 1(-0.75,0) 2(0.75,0)
  silkscreen extent -1.05,-0.75 1.05,0.75
DIO_SOD323 [mm]
  rect 1.06x0.54 smd mask+0: 1(-1.07,0) 2(1.07,0)
  silkscreen extent -0.9,-0.72 0.9,0.72
DIO_SOT23 [mm]
  rect 1x1.4 smd mask+0: 1(-0.95,-1.1) 2(0.95,-1.1) 3(0,1.1)
  silkscreen extent -1.63,-0.82 1.63,0.82
ICC_LFBGA436_18X18_P080_H1P70_STM32MP257_CODE-B0D1 [mm] "MCD02000"
  round 0.3 smd paste+0.025 mask+0: A1(-8.4,8.4) A2(-7.6,8.4) A3(-6.8,8.4) A4(-6,8.4) A7(-3.6,8.4) A8(-2.8,8.4) A11(-0.4,8.4) A12(0.4,8.4) A15(2.8,8.4) A16(3.6,8.4) A19(6,8.4) A20(6.8,8.4) A21(7.6,8.4) A22(8.4,8.4) AA1(-8.4,-7.6) AA2(-7.6,-7.6) AA3(-6.8,-7.6) AA4(-6,-7.6) AA6(-4.4,-7.6) AA7(-3.6,-7.6) AA8(-2.8,-7.6) AA10(-1.2,-7.6) AA11(-0.4,-7.6) AA12(0.4,-7.6) AA14(2,-7.6) AA15(2.8,-7.6) AA16(3.6,-7.6) AA18(5.2,-7.6) AA19(6,-7.6) AA20(6.8,-7.6) AA21(7.6,-7.6) AA22(8.4,-7.6) AB1(-8.4,-8.4) AB2(-7.6,-8.4) AB3(-6.8,-8.4) AB4(-6,-8.4) AB7(-3.6,-8.4) AB8(-2.8,-8.4) AB11(-0.4,-8.4) AB12(0.4,-8.4) AB15(2.8,-8.4) AB16(3.6,-8.4) AB19(6,-8.4) AB20(6.8,-8.4) AB21(7.6,-8.4) AB22(8.4,-8.4) B1(-8.4,7.6) B2(-7.6,7.6) B3(-6.8,7.6) B4(-6,7.6) B5(-5.2,7.6) B7(-3.6,7.6) B8(-2.8,7.6) B9(-2,7.6) B11(-0.4,7.6) B12(0.4,7.6) B13(1.2,7.6) B15(2.8,7.6) B16(3.6,7.6) B17(4.4,7.6) B19(6,7.6) B20(6.8,7.6) B21(7.6,7.6) B22(8.4,7.6) C1(-8.4,6.8) C2(-7.6,6.8) C3(-6.8,6.8) C4(-6,6.8) C5(-5.2,6.8) C6(-4.4,6.8) C7(-3.6,6.8) C8(-2.8,6.8) C9(-2,6.8) C10(-1.2,6.8) C11(-0.4,6.8) C12(0.4,6.8) C13(1.2,6.8) C14(2,6.8) C15(2.8,6.8) C16(3.6,6.8) C17(4.4,6.8) C18(5.2,6.8) C19(6,6.8) C20(6.8,6.8) C21(7.6,6.8) C22(8.4,6.8) D1(-8.4,6) D2(-7.6,6) D3(-6.8,6) D4(-6,6) D5(-5.2,6) D6(-4.4,6) D7(-3.6,6) D8(-2.8,6) D9(-2,6) D10(-1.2,6) D11(-0.4,6) D12(0.4,6) D13(1.2,6) D14(2,6) D15(2.8,6) D16(3.6,6) D17(4.4,6) D18(5.2,6) D19(6,6) D20(6.8,6) D21(7.6,6) D22(8.4,6) E3(-6.8,5.2) E4(-6,5.2) E5(-5.2,5.2) E6(-4.4,5.2) E7(-3.6,5.2) E8(-2.8,5.2) E9(-2,5.2) E10(-1.2,5.2) E11(-0.4,5.2) E12(0.4,5.2) E13(1.2,5.2) E14(2,5.2) E15(2.8,5.2) E16(3.6,5.2) E17(4.4,5.2) E18(5.2,5.2) E19(6,5.2) E20(6.8,5.2) E21(7.6,5.2) F2(-7.6,4.4) F3(-6.8,4.4) F4(-6,4.4) F5(-5.2,4.4) F6(-4.4,4.4) F7(-3.6,4.4) F8(-2.8,4.4) F9(-2,4.4) F10(-1.2,4.4) F11(-0.4,4.4) F12(0.4,4.4) F13(1.2,4.4) F14(2,4.4) F15(2.8,4.4) F16(3.6,4.4) F17(4.4,4.4) F18(5.2,4.4) F19(6,4.4) F20(6.8,4.4) G1(-8.4,3.6) G2(-7.6,3.6) G3(-6.8,3.6) G4(-6,3.6) G5(-5.2,3.6) G6(-4.4,3.6) G7(-3.6,3.6) G8(-2.8,3.6) G9(-2,3.6) G10(-1.2,3.6) G11(-0.4,3.6) G12(0.4,3.6) G13(1.2,3.6) G14(2,3.6) G15(2.8,3.6) G16(3.6,3.6) G17(4.4,3.6) G18(5.2,3.6) G19(6,3.6) G20(6.8,3.6) G21(7.6,3.6) G22(8.4,3.6) H1(-8.4,2.8) H2(-7.6,2.8) H3(-6.8,2.8) H4(-6,2.8) H5(-5.2,2.8) H6(-4.4,2.8) H7(-3.6,2.8) H8(-2.8,2.8) H9(-2,2.8) H10(-1.2,2.8) H11(-0.4,2.8) H12(0.4,2.8) H13(1.2,2.8) H14(2,2.8) H15(2.8,2.8) H16(3.6,2.8) H17(4.4,2.8) H18(5.2,2.8) H19(6,2.8) H20(6.8,2.8) H21(7.6,2.8) H22(8.4,2.8) J3(-6.8,2) J4(-6,2) J5(-5.2,2) J6(-4.4,2) J7(-3.6,2) J8(-2.8,2) J9(-2,2) J10(-1.2,2) J11(-0.4,2) J12(0.4,2) J13(1.2,2) J14(2,2) J15(2.8,2) J16(3.6,2) J17(4.4,2) J18(5.2,2) J19(6,2) J20(6.8,2) J21(7.6,2) K2(-7.6,1.2) K3(-6.8,1.2) K4(-6,1.2) K5(-5.2,1.2) K6(-4.4,1.2) K7(-3.6,1.2) K8(-2.8,1.2) K9(-2,1.2) K10(-1.2,1.2) K11(-0.4,1.2) K12(0.4,1.2) K13(1.2,1.2) K14(2,1.2) K15(2.8,1.2) K16(3.6,1.2) K17(4.4,1.2) K18(5.2,1.2) K19(6,1.2) K20(6.8,1.2) L1(-8.4,0.4) L2(-7.6,0.4) L3(-6.8,0.4) L4(-6,0.4) L5(-5.2,0.4) L6(-4.4,0.4) L7(-3.6,0.4) L8(-2.8,0.4) L9(-2,0.4) L10(-1.2,0.4) L11(-0.4,0.4) L12(0.4,0.4) L13(1.2,0.4) L14(2,0.4) L15(2.8,0.4) L16(3.6,0.4) L17(4.4,0.4) L18(5.2,0.4) L19(6,0.4) L20(6.8,0.4) L21(7.6,0.4) L22(8.4,0.4) M1(-8.4,-0.4) M2(-7.6,-0.4) M3(-6.8,-0.4) M4(-6,-0.4) M5(-5.2,-0.4) M6(-4.4,-0.4) M7(-3.6,-0.4) M8(-2.8,-0.4) M9(-2,-0.4) M10(-1.2,-0.4) M11(-0.4,-0.4) M12(0.4,-0.4) M13(1.2,-0.4) M14(2,-0.4) M15(2.8,-0.4) M16(3.6,-0.4) M17(4.4,-0.4) M18(5.2,-0.4) M19(6,-0.4) M20(6.8,-0.4) M21(7.6,-0.4) M22(8.4,-0.4) N3(-6.8,-1.2) N4(-6,-1.2) N5(-5.2,-1.2) N6(-4.4,-1.2) N7(-3.6,-1.2) N8(-2.8,-1.2) N9(-2,-1.2) N10(-1.2,-1.2) N11(-0.4,-1.2) N12(0.4,-1.2) N13(1.2,-1.2) N14(2,-1.2) N15(2.8,-1.2) N16(3.6,-1.2) N17(4.4,-1.2) N18(5.2,-1.2) N19(6,-1.2) N20(6.8,-1.2) N21(7.6,-1.2) P2(-7.6,-2) P3(-6.8,-2) P4(-6,-2) P5(-5.2,-2) P6(-4.4,-2) P7(-3.6,-2) P8(-2.8,-2) P9(-2,-2) P10(-1.2,-2) P11(-0.4,-2) P12(0.4,-2) P13(1.2,-2) P14(2,-2) P15(2.8,-2) P16(3.6,-2) P17(4.4,-2) P18(5.2,-2) P19(6,-2) P20(6.8,-2) R1(-8.4,-2.8) R2(-7.6,-2.8) R3(-6.8,-2.8) R4(-6,-2.8) R5(-5.2,-2.8) R6(-4.4,-2.8) R7(-3.6,-2.8) R8(-2.8,-2.8) R9(-2,-2.8) R10(-1.2,-2.8) R11(-0.4,-2.8) R12(0.4,-2.8) R13(1.2,-2.8) R14(2,-2.8) R15(2.8,-2.8) R16(3.6,-2.8) R17(4.4,-2.8) R18(5.2,-2.8) R19(6,-2.8) R20(6.8,-2.8) R21(7.6,-2.8) R22(8.4,-2.8) T1(-8.4,-3.6) T2(-7.6,-3.6) T3(-6.8,-3.6) T4(-6,-3.6) T5(-5.2,-3.6) T6(-4.4,-3.6) T7(-3.6,-3.6) T8(-2.8,-3.6) T9(-2,-3.6) T10(-1.2,-3.6) T11(-0.4,-3.6) T12(0.4,-3.6) T13(1.2,-3.6) T14(2,-3.6) T15(2.8,-3.6) T16(3.6,-3.6) T17(4.4,-3.6) T18(5.2,-3.6) T19(6,-3.6) T20(6.8,-3.6) T21(7.6,-3.6) T22(8.4,-3.6) U3(-6.8,-4.4) U4(-6,-4.4) U5(-5.2,-4.4) U6(-4.4,-4.4) U7(-3.6,-4.4) U8(-2.8,-4.4) U9(-2,-4.4) U10(-1.2,-4.4) U11(-0.4,-4.4) U12(0.4,-4.4) U13(1.2,-4.4) U14(2,-4.4) U15(2.8,-4.4) U16(3.6,-4.4) U17(4.4,-4.4) U18(5.2,-4.4) U19(6,-4.4) U20(6.8,-4.4) U21(7.6,-4.4) V2(-7.6,-5.2) V3(-6.8,-5.2) V4(-6,-5.2) V5(-5.2,-5.2) V6(-4.4,-5.2) V7(-3.6,-5.2) V8(-2.8,-5.2) V9(-2,-5.2) V10(-1.2,-5.2) V11(-0.4,-5.2) V12(0.4,-5.2) V13(1.2,-5.2) V14(2,-5.2) V15(2.8,-5.2) V16(3.6,-5.2) V17(4.4,-5.2) V18(5.2,-5.2) V19(6,-5.2) V20(6.8,-5.2) W1(-8.4,-6) W2(-7.6,-6) W3(-6.8,-6) W4(-6,-6) W5(-5.2,-6) W6(-4.4,-6) W7(-3.6,-6) W8(-2.8,-6) W9(-2,-6) W10(-1.2,-6) W11(-0.4,-6) W12(0.4,-6) W13(1.2,-6) W14(2,-6) W15(2.8,-6) W16(3.6,-6) W17(4.4,-6) W18(5.2,-6) W19(6,-6) W20(6.8,-6) W21(7.6,-6) W22(8.4,-6) Y1(-8.4,-6.8) Y2(-7.6,-6.8) Y3(-6.8,-6.8) Y4(-6,-6.8) Y5(-5.2,-6.8) Y6(-4.4,-6.8) Y7(-3.6,-6.8) Y8(-2.8,-6.8) Y9(-2,-6.8) Y10(-1.2,-6.8) Y11(-0.4,-6.8) Y12(0.4,-6.8) Y13(1.2,-6.8) Y14(2,-6.8) Y15(2.8,-6.8) Y16(3.6,-6.8) Y17(4.4,-6.8) Y18(5.2,-6.8) Y19(6,-6.8) Y20(6.8,-6.8) Y21(7.6,-6.8) Y22(8.4,-6.8)
  silkscreen extent -9.25,-9.1 9.1,9.25
ICC_P-WFBGA153_13X11P5_P050 [mm]
  round 0.23 smd mask+0: A1(-3.25,-3.25) A2(-3.25,-2.75) A3(-3.25,-2.25) A4(-3.25,-1.75) A5(-3.25,-1.25) A6(-3.25,-0.75) A7(-3.25,-0.25) A8(-3.25,0.25) A9(-3.25,0.75) A10(-3.25,1.25) A11(-3.25,1.75) A12(-3.25,2.25) A13(-3.25,2.75) A14(-3.25,3.25) B1(-2.75,-3.25) B2(-2.75,-2.75) B3(-2.75,-2.25) B4(-2.75,-1.75) B5(-2.75,-1.25) B6(-2.75,-0.75) B7(-2.75,-0.25) B8(-2.75,0.25) B9(-2.75,0.75) B10(-2.75,1.25) B11(-2.75,1.75) B12(-2.75,2.25) B13(-2.75,2.75) B14(-2.75,3.25) C1(-2.25,-3.25) C2(-2.25,-2.75) C3(-2.25,-2.25) C4(-2.25,-1.75) C5(-2.25,-1.25) C6(-2.25,-0.75) C7(-2.25,-0.25) C8(-2.25,0.25) C9(-2.25,0.75) C10(-2.25,1.25) C11(-2.25,1.75) C12(-2.25,2.25) C13(-2.25,2.75) C14(-2.25,3.25) D1(-1.75,-3.25) D2(-1.75,-2.75) D3(-1.75,-2.25) D4(-1.75,-1.75) D12(-1.75,2.25) D13(-1.75,2.75) D14(-1.75,3.25) E1(-1.25,-3.25) E2(-1.25,-2.75) E3(-1.25,-2.25) E5(-1.25,-1.25) E6(-1.25,-0.75) E7(-1.25,-0.25) E8(-1.25,0.25) E9(-1.25,0.75) E10(-1.25,1.25) E12(-1.25,2.25) E13(-1.25,2.75) E14(-1.25,3.25) F1(-0.75,-3.25) F2(-0.75,-2.75) F3(-0.75,-2.25) F5(-0.75,-1.25) F10(-0.75,1.25) F12(-0.75,2.25) F13(-0.75,2.75) F14(-0.75,3.25) G1(-0.25,-3.25) G2(-0.25,-2.75) G3(-0.25,-2.25) G5(-0.25,-1.25) G10(-0.25,1.25) G12(-0.25,2.25) G13(-0.25,2.75) G14(-0.25,3.25) H1(0.25,-3.25) H2(0.25,-2.75) H3(0.25,-2.25) H5(0.25,-1.25) H10(0.25,1.25) H12(0.25,2.25) H13(0.25,2.75) H14(0.25,3.25) J1(0.75,-3.25) J2(0.75,-2.75) J3(0.75,-2.25) J5(0.75,-1.25) J10(0.75,1.25) J12(0.75,2.25) J13(0.75,2.75) J14(0.75,3.25) K1(1.25,-3.25) K2(1.25,-2.75) K3(1.25,-2.25) K5(1.25,-1.25) K6(1.25,-0.75) K7(1.25,-0.25) K8(1.25,0.25) K9(1.25,0.75) K10(1.25,1.25) K12(1.25,2.25) K13(1.25,2.75) K14(1.25,3.25) L1(1.75,-3.25) L2(1.75,-2.75) L3(1.75,-2.25) L12(1.75,2.25) L13(1.75,2.75) L14(1.75,3.25) M1(2.25,-3.25) M2(2.25,-2.75) M3(2.25,-2.25) M4(2.25,-1.75) M5(2.25,-1.25) M6(2.25,-0.75) M7(2.25,-0.25) M8(2.25,0.25) M9(2.25,0.75) M10(2.25,1.25) M11(2.25,1.75) M12(2.25,2.25) M13(2.25,2.75) M14(2.25,3.25) N1(2.75,-3.25) N2(2.75,-2.75) N3(2.75,-2.25) N4(2.75,-1.75) N5(2.75,-1.25) N6(2.75,-0.75) N7(2.75,-0.25) N8(2.75,0.25) N9(2.75,0.75) N10(2.75,1.25) N11(2.75,1.75) N12(2.75,2.25) N13(2.75,2.75) N14(2.75,3.25) P1(3.25,-3.25) P2(3.25,-2.75) P3(3.25,-2.25) P4(3.25,-1.75) P5(3.25,-1.25) P6(3.25,-0.75) P7(3.25,-0.25) P8(3.25,0.25) P9(3.25,0.75) P10(3.25,1.25) P11(3.25,1.75) P12(3.25,2.25) P13(3.25,2.75) P14(3.25,3.25)
  silkscreen extent -6.78,-6.02 6.63,5.87
ICC_QFN56-EPAD_6P5X6P5_P040 [mm] "MCD-03000"
  rect 0.55x0.21 smd mask+0: 1(-3.245,2.6) 14(-3.245,-2.6) 29(3.245,-2.6) 42(3.245,2.6)
  rect 0.7x0.21 smd mask+0: 2(-3.17,2.2) 3(-3.17,1.8) 4(-3.17,1.4) 5(-3.17,1) 6(-3.17,0.6) 7(-3.17,0.2) 8(-3.17,-0.2) 9(-3.17,-0.6) 10(-3.17,-1) 11(-3.17,-1.4) 12(-3.17,-1.8) 13(-3.17,-2.2) 30(3.17,-2.2) 31(3.17,-1.8) 32(3.17,-1.4) 33(3.17,-1) 34(3.17,-0.6) 35(3.17,-0.2) 36(3.17,0.2) 37(3.17,0.6) 38(3.17,1) 39(3.17,1.4) 40(3.17,1.8) 41(3.17,2.2)
  rect 0.21x0.55 smd mask+0: 15(-2.6,-3.245) 28(2.6,-3.245) 43(2.6,3.245) 56(-2.6,3.245)
  rect 0.21x0.7 smd mask+0: 16(-2.2,-3.17) 17(-1.8,-3.17) 18(-1.4,-3.17) 19(-1,-3.17) 20(-0.6,-3.17) 21(-0.2,-3.17) 22(0.2,-3.17) 23(0.6,-3.17) 24(1,-3.17) 25(1.4,-3.17) 26(1.8,-3.17) 27(2.2,-3.17) 44(2.2,3.17) 45(1.8,3.17) 46(1.4,3.17) 47(1,3.17) 48(0.6,3.17) 49(0.2,3.17) 50(-0.2,3.17) 51(-0.6,3.17) 52(-1,3.17) 53(-1.4,3.17) 54(-1.8,3.17) 55(-2.2,3.17)
  rect 4.7x4.7 smd mask+0: 57(0,0)
  silkscreen extent -3.44,3 -3.01,3.42
ICC_TFBGA200_10X14P5_P080_H1P05_PS0P3 [mm] "MCD-04012"
  round 0.3 smd mask+0: A1(-4.4,6.825) A2(-3.6,6.825) A3(-2.8,6.825) A4(-2,6.825) A5(-1.2,6.825) A8(1.2,6.825) A9(2,6.825) A10(2.8,6.825) A11(3.6,6.825) A12(4.4,6.825) AA1(-4.4,-6.175) AA2(-3.6,-6.175) AA3(-2.8,-6.175) AA4(-2,-6.175) AA5(-1.2,-6.175) AA8(1.2,-6.175) AA9(2,-6.175) AA10(2.8,-6.175) AA11(3.6,-6.175) AA12(4.4,-6.175) AB1(-4.4,-6.825) AB2(-3.6,-6.825) AB3(-2.8,-6.825) AB4(-2,-6.825) AB5(-1.2,-6.825) AB8(1.2,-6.825) AB9(2,-6.825) AB10(2.8,-6.825) AB11(3.6,-6.825) AB12(4.4,-6.825) B1(-4.4,6.175) B2(-3.6,6.175) B3(-2.8,6.175) B4(-2,6.175) B5(-1.2,6.175) B8(1.2,6.175) B9(2,6.175) B10(2.8,6.175) B11(3.6,6.175) B12(4.4,6.175) C1(-4.4,5.525) C2(-3.6,5.525) C3(-2.8,5.525) C4(-2,5.525) C5(-1.2,5.525) C8(1.2,5.525) C9(2,5.525) C10(2.8,5.525) C11(3.6,5.525) C12(4.4,5.525) D1(-4.4,4.875) D2(-3.6,4.875) D3(-2.8,4.875) D4(-2,4.875) D5(-1.2,4.875) D8(1.2,4.875) D9(2,4.875) D10(2.8,4.875) D11(3.6,4.875) D12(4.4,4.875) E1(-4.4,4.225) E2(-3.6,4.225) E3(-2.8,4.225) E4(-2,4.225) E5(-1.2,4.225) E8(1.2,4.225) E9(2,4.225) E10(2.8,4.225) E11(3.6,4.225) E12(4.4,4.225) F1(-4.4,3.575) F2(-3.6,3.575) F3(-2.8,3.575) F4(-2,3.575) F5(-1.2,3.575) F8(1.2,3.575) F9(2,3.575) F10(2.8,3.575) F11(3.6,3.575) F12(4.4,3.575) G1(-4.4,2.925) G2(-3.6,2.925) G3(-2.8,2.925) G4(-2,2.925) G5(-1.2,2.925) G8(1.2,2.925) G9(2,2.925) G10(2.8,2.925) G11(3.6,2.925) G12(4.4,2.925) H1(-4.4,2.275) H2(-3.6,2.275) H3(-2.8,2.275) H4(-2,2.275) H5(-1.2,2.275) H8(1.2,2.275) H9(2,2.275) H10(2.8,2.275) H11(3.6,2.275) H12(4.4,2.275) J1(-4.4,1.625) J2(-3.6,1.625) J3(-2.8,1.625) J4(-2,1.625) J5(-1.2,1.625) J8(1.2,1.625) J9(2,1.625) J10(2.8,1.625) J11(3.6,1.625) J12(4.4,1.625) K1(-4.4,0.975) K2(-3.6,0.975) K3(-2.8,0.975) K4(-2,0.975) K5(-1.2,0.975) K8(1.2,0.975) K9(2,0.975) K10(2.8,0.975) K11(3.6,0.975) K12(4.4,0.975) N1(-4.4,-0.975) N2(-3.6,-0.975) N3(-2.8,-0.975) N4(-2,-0.975) N5(-1.2,-0.975) N8(1.2,-0.975) N9(2,-0.975) N10(2.8,-0.975) N11(3.6,-0.975) N12(4.4,-0.975) P1(-4.4,-1.625) P2(-3.6,-1.625) P3(-2.8,-1.625) P4(-2,-1.625) P5(-1.2,-1.625) P8(1.2,-1.625) P9(2,-1.625) P10(2.8,-1.625) P11(3.6,-1.625) P12(4.4,-1.625) R1(-4.4,-2.275) R2(-3.6,-2.275) R3(-2.8,-2.275) R4(-2,-2.275) R5(-1.2,-2.275) R8(1.2,-2.275) R9(2,-2.275) R10(2.8,-2.275) R11(3.6,-2.275) R12(4.4,-2.275) T1(-4.4,-2.925) T2(-3.6,-2.925) T3(-2.8,-2.925) T4(-2,-2.925) T5(-1.2,-2.925) T8(1.2,-2.925) T9(2,-2.925) T10(2.8,-2.925) T11(3.6,-2.925) T12(4.4,-2.925) U1(-4.4,-3.575) U2(-3.6,-3.575) U3(-2.8,-3.575) U4(-2,-3.575) U5(-1.2,-3.575) U8(1.2,-3.575) U9(2,-3.575) U10(2.8,-3.575) U11(3.6,-3.575) U12(4.4,-3.575) V1(-4.4,-4.225) V2(-3.6,-4.225) V3(-2.8,-4.225) V4(-2,-4.225) V5(-1.2,-4.225) V8(1.2,-4.225) V9(2,-4.225) V10(2.8,-4.225) V11(3.6,-4.225) V12(4.4,-4.225) W1(-4.4,-4.875) W2(-3.6,-4.875) W3(-2.8,-4.875) W4(-2,-4.875) W5(-1.2,-4.875) W8(1.2,-4.875) W9(2,-4.875) W10(2.8,-4.875) W11(3.6,-4.875) W12(4.4,-4.875) Y1(-4.4,-5.525) Y2(-3.6,-5.525) Y3(-2.8,-5.525) Y4(-2,-5.525) Y5(-1.2,-5.525) Y8(1.2,-5.525) Y9(2,-5.525) Y10(2.8,-5.525) Y11(3.6,-5.525) Y12(4.4,-5.525)
  silkscreen extent -5.2,-7.3 5.05,7.45
IND_2016_MURATA_LQM2MPN2R2NG0 [mm]
  rect 0.8x1.8 smd mask+0: 1(-0.8,0) 2(0.8,0)
  silkscreen extent -0.28,-0.87 0.28,0.87
IND_2520_TOKO_DFE252012P [mm]
  rect 0.8x2 smd mask+0: 1(-1,0) 2(1,0)
  silkscreen extent -1.35,-1.12 1.35,1.12
LED_0603_OSRAM_LG-Q396-PS-35_GREEN_1A2K_H0P4 [mm]
  rect 0.8x0.8 smd mask+0: 1(-0.75,0) 2(0.75,0)
  silkscreen extent -0.85,-0.53 1.28,0.53
LINK200 [mm]
  rect 0.2x0.35 smd paste-10 mask+0: 1(0,-0.225) 2(0,0.225)
R0201_H0P23 [mm]
  rect 0.4x0.5 smd mask+0: 1(-0.3,0) 2(0.3,0)
R0402 [mm]
  rect 0.51x0.7 smd mask+0: 1(-0.45,0) 2(0.45,0)
R0603 [mm]
  rect 0.64x1 smd mask+0: 1(-0.7,0) 2(0.7,0)
  silkscreen extent -1.05,-0.58 1.05,0.58
SWI_WE_434121025816 [mm] "MCD-03492"
  rect 1.5x1.4 smd: 1(-3.25,0) 2(3.25,0)
  silkscreen extent -3,-1.95 3,1.95
TP_SMD_1MM [mm]
  round 1 smd paste-10 mask+0: 1(0,0)
  silkscreen extent -0.7,-0.7 0.7,0.7

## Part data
B2: library part MCD-03492, "Switch tactile, SPST-NO, 50mA, 12V, 6x3.8mm"
C1 C2 C3 C4 C5 C6 C7 C8 C9 C10 C11 C12 C13 C14 C15 C16 C17 C25 C31 C44 C45 C46 C47 C52 C53 C54 C55 C56 C57 C58 C59 C60 C67: library part MCD-02377, "Capacitor, MLCC, 1uF, 6.3V, X5R, +/-20%, 0201, T=0,3mm"
C18 C42: library part MCD-01796, "Capacitor, Tantalum, 100uF, 6V3, 40mR, +/-20%,  Type_B (3528 metric), T=1.9mm"
C19 C21 C152 C157 C186 C187 C193 C204 C206 C207: library part MCD-03139, "Capacitor, MLCC, 22uF, 10V, X5R, +/-20%, 0805, T=1,25mm"
C20 C29 C30 C32 C38 C184 C199: library part MCD-00099, "Capacitor, MLCC, 10uF, 10V, X5R, +/-10%, 0603, T=0,8mm"
C22 C23 C24 C26 C27 C28 C34 C35 C36 C37 C41 C183 C200 C202: library part MCD-00100, "Capacitor, MLCC, 22uF, 6V3, X5R, +/-20%, 0603, T=0,8mm"
C33: library part MCD-00011, "Capacitor, MLCC, 10nF, 16V, X7R, 10%, 0402, T=0.5mm"
C39 C43 C153 C154 C188: library part MCD-00095, "Capacitor, MLCC, 1uF, 25V, X5R, +/-10%, 0402, T=0.5mm"
C40: library part MCD-03140, "Capacitor, MLCC, 10uF, 6.3V, X5R, +/-20%, 0402, T=0.5mm"
C50 C101 C102 C103 C104 C105 C106 C107 C108 C124 C125 C130 C131 C151 C175 C177 C179 C182: library part MCD-00006, "Capacitor, MLCC, 100nF, 16V, X7R, +/-10%, 0402, T=0.5mm"
C51 C100 C123 C176: library part MCD-01341, "Capacitor, MLCC, 10uF, 6V3, X5R, +/-20%, 0603, T=0,8mm"
C61: library part MCD-01534, "Capacitor, MLCC, 4,7uF, 6V3, X5R, +/-20%, 0201, T=0.5mm"
C62 C63 C64 C65 C66 C68 C69 C70 C71 C72 C73 C74 C75 C89 C96 C97 C98 C212 C234 C275 C285: library part MCD-01535, "Capacitor, MLCC,100nF, 10V, X7R, +/-10%, 0201, T=0.3mm"
C79: library part MCD-02235, "Capacitor, MLCC, 2.2uF, 10V, X5R,+/-10%, 0201, T=0.5mm"
C81 C86 C90 C92: library part MCD-00674, "Capacitor, MLCC, 6.8pF, 50V, NPO, +-0.25pF, 0402, T=0.5mm"
C87: library part MCD-00006, "Capacitor,100nF,16V,X7R,10%,0402"
C88: library part MCD-01823, "Capacitor, MLCC, 2.2uF, 6V3, X5R,+/-10%, 0402, T=0.5mm"
C91 C141 C142 C156 C189 C190 C208 C209 C217: library part MCD-01356, "Capacitor, MLCC, 4.7uF, 6V3, X5R, +/-20%, 0402, T=0.5mm"
C155: library part MCD-02198, "Capacitor, MLCC, 10nF, 50V, X7R, +/-10%, 0402, T=0.5mm"
C178 C180 C181: library part MCD-02606, "Capacitor, MLCC, 2.2uF, 6.3V, X5R, +/-10%, 0402, T=0.5mm"
CN12: library part MCD-00655, "Header 2 circuits, 1.25mm Pitch ,  Vertical, with Friction Lock"
D5: library part MCD-00034
D6: library part MCD-03280, "Diode, Schottky, Dual Common Cathode, 0V3, 300mA, 40V, SOT-23"
L1 L6: library part MCD-03143, "Inductor, 2.2uH, +/-20%, Itemp= 1700mA, Isat= 2400mA, 0R140, 0806, T=1mm"
L2 L4: library part MCD-03142, "Inductor, 0.68uH, +/-20%, Itemp= 3900mA, Isat= 5400mA, 0R031, 1008, T=1.2mm"
L3 L5 L7: library part MCD-03141, "Inductor, 0.68uH, +/-20%, Itemp= 3100mA, Isat= 4300mA, 0R043, 0806, T=1mm"
LD11: library part MCD-00588, "LED Green, 0603 SMD, Forward Voltage Typ=2V, Max=2.5V"
LNK1 LNK2 LNK4 LNK7 LNK8 LNK11: library part MCD-02777, "Track link on PCB 200um width for layout routing"
R1 R163: library part MCD-02253, "Resistor, 240R, 0201, +/-1%, 1/20W"
R2 R46 R57 R59 R60 R64 R75 R81 R267 R269 R286: library part MCD-00052, "Resistor,0R,0402,5%,1/16W"
R27 R37 R44 R49 R248 R272: library part MCD-00053, "Resistor,10K,0402,1%,1/16W"
R66: library part MCD-00058, "Resistor, 20R, 0402, +/-1%, 1/16W"
R67: library part MCD-00052, "Resistor, 0R, 0402, +/-5%, 1/16W"
R156: library part MCD-00053, "Resistor, 10K, 0402, +/-1%, 1/16W"
R210: library part MCD-00441, "Resistor,270R,0402,1%,1/16W"
R249: library part MCD-00056, "Resistor, 0R, 0603, +/-5%, 1/10W"
R260 R261: library part MCD-00068, "Resistor,1K5,0402,1%,1/16W"
TP9: library part MCD-00074, "Test Point 1mm"
U2: library part MCD-04160, "Memory, LPDDR4 SDRAM,1V8, 32Gbit, 2133MHz"
U24: library part MCD-02799, "Memory, eMMC, 4GB, 15nm ,WFBGA , 153 pins"
U26: library part MCD-03000, "STPMIC2"
U27: library part MCD-02000, "MPU, ARM Cortex-A35 + M33 32-bit MPU, 808KB RAM, With Crypto"
X1: library part MCD-01479, "Crystal, 32.768kHz, 6pF, +/-20ppm, 80K, 2.05x1.2mm"
X2: library part MCD-02344, "Crystal, 40MHz, 6pF, +/-20ppm, 80R, 1.6x1.2mm"

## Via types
v1: diameter 0.55, hole 0.35, Top Layer to Bottom Layer, 387 vias
v2: diameter 0.4, hole 0.2, Top Layer to Bottom Layer, tented both sides, 173 vias
v3: diameter 0.5, hole 0.2, Top Layer to Bottom Layer, 146 vias
v4: diameter 0.4, hole 0.2, Top Layer to Bottom Layer, 129 vias
v5: diameter 0.5, hole 0.25, Top Layer to Bottom Layer, 3 vias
